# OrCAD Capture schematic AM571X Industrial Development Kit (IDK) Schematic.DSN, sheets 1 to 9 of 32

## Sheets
1 Pg23: USB JTAG: size C; title: AM571x Industrial Development Kit (IDK) EVM - TMDXIDK5718; rev: 1.3B; company: Texas Instruments; note: 3M0000; note: Catalog Processors BU; note: Final
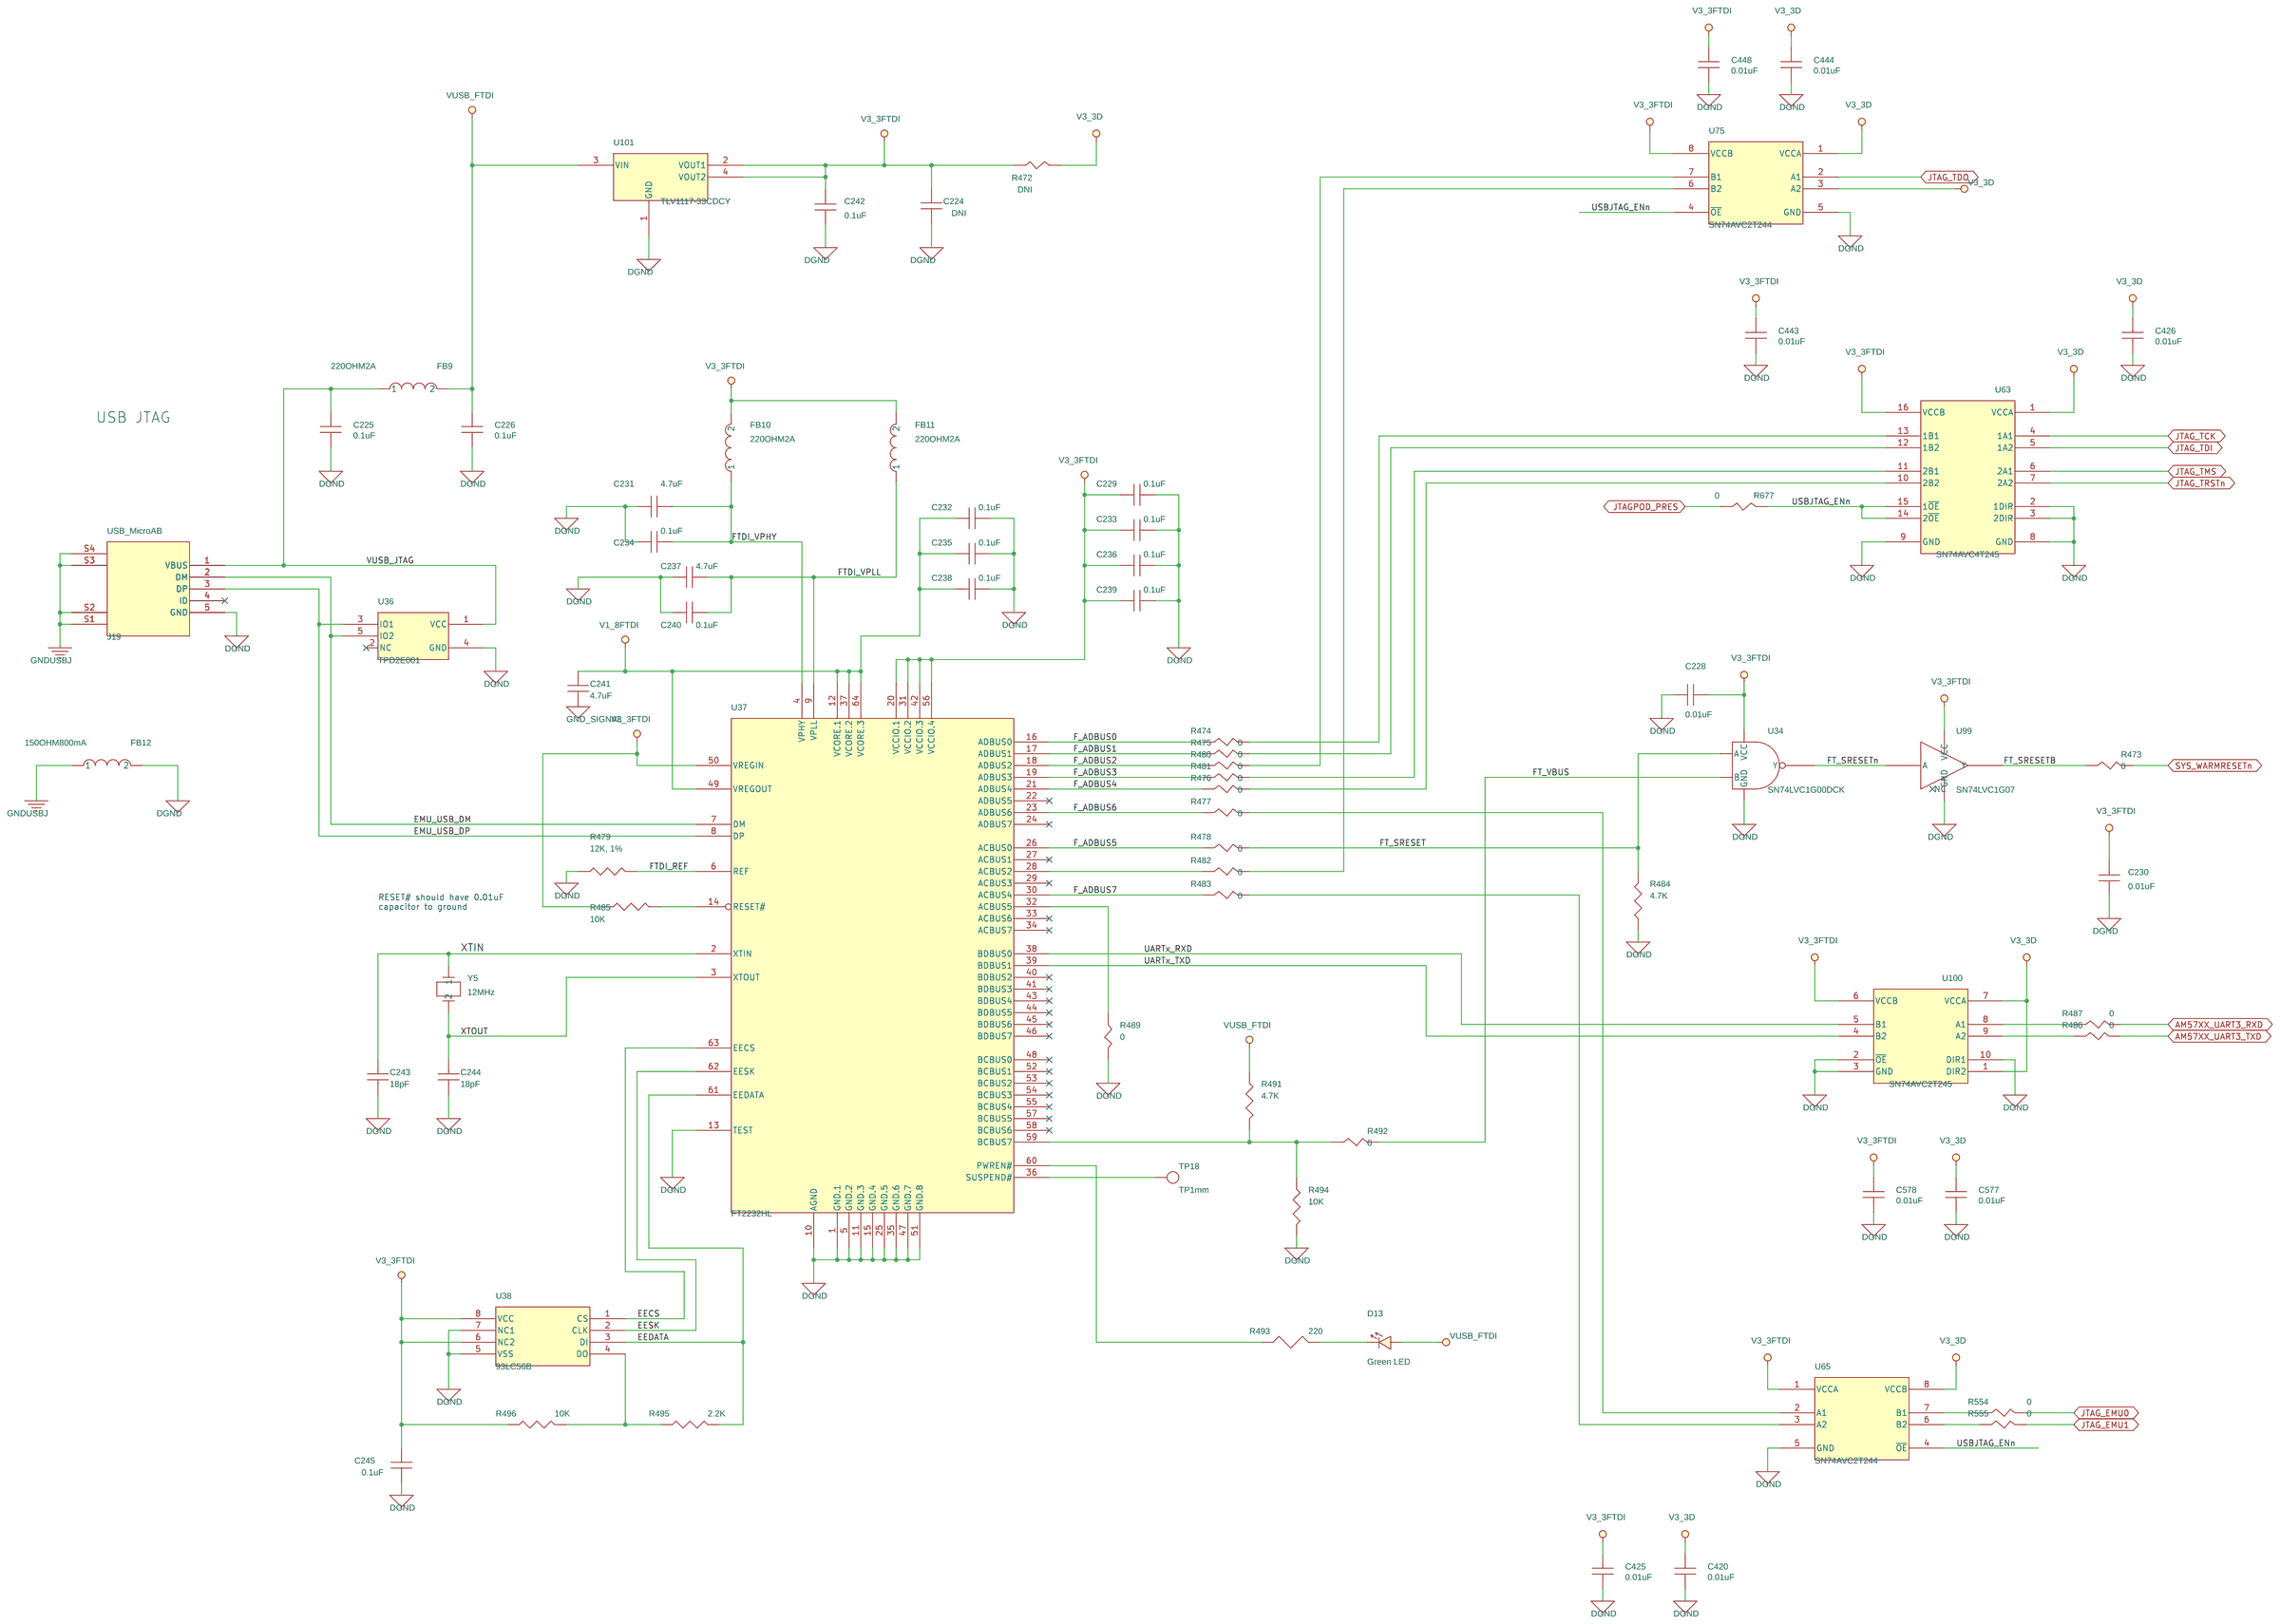
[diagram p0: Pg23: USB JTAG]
2 Pg24: eMMC: size C
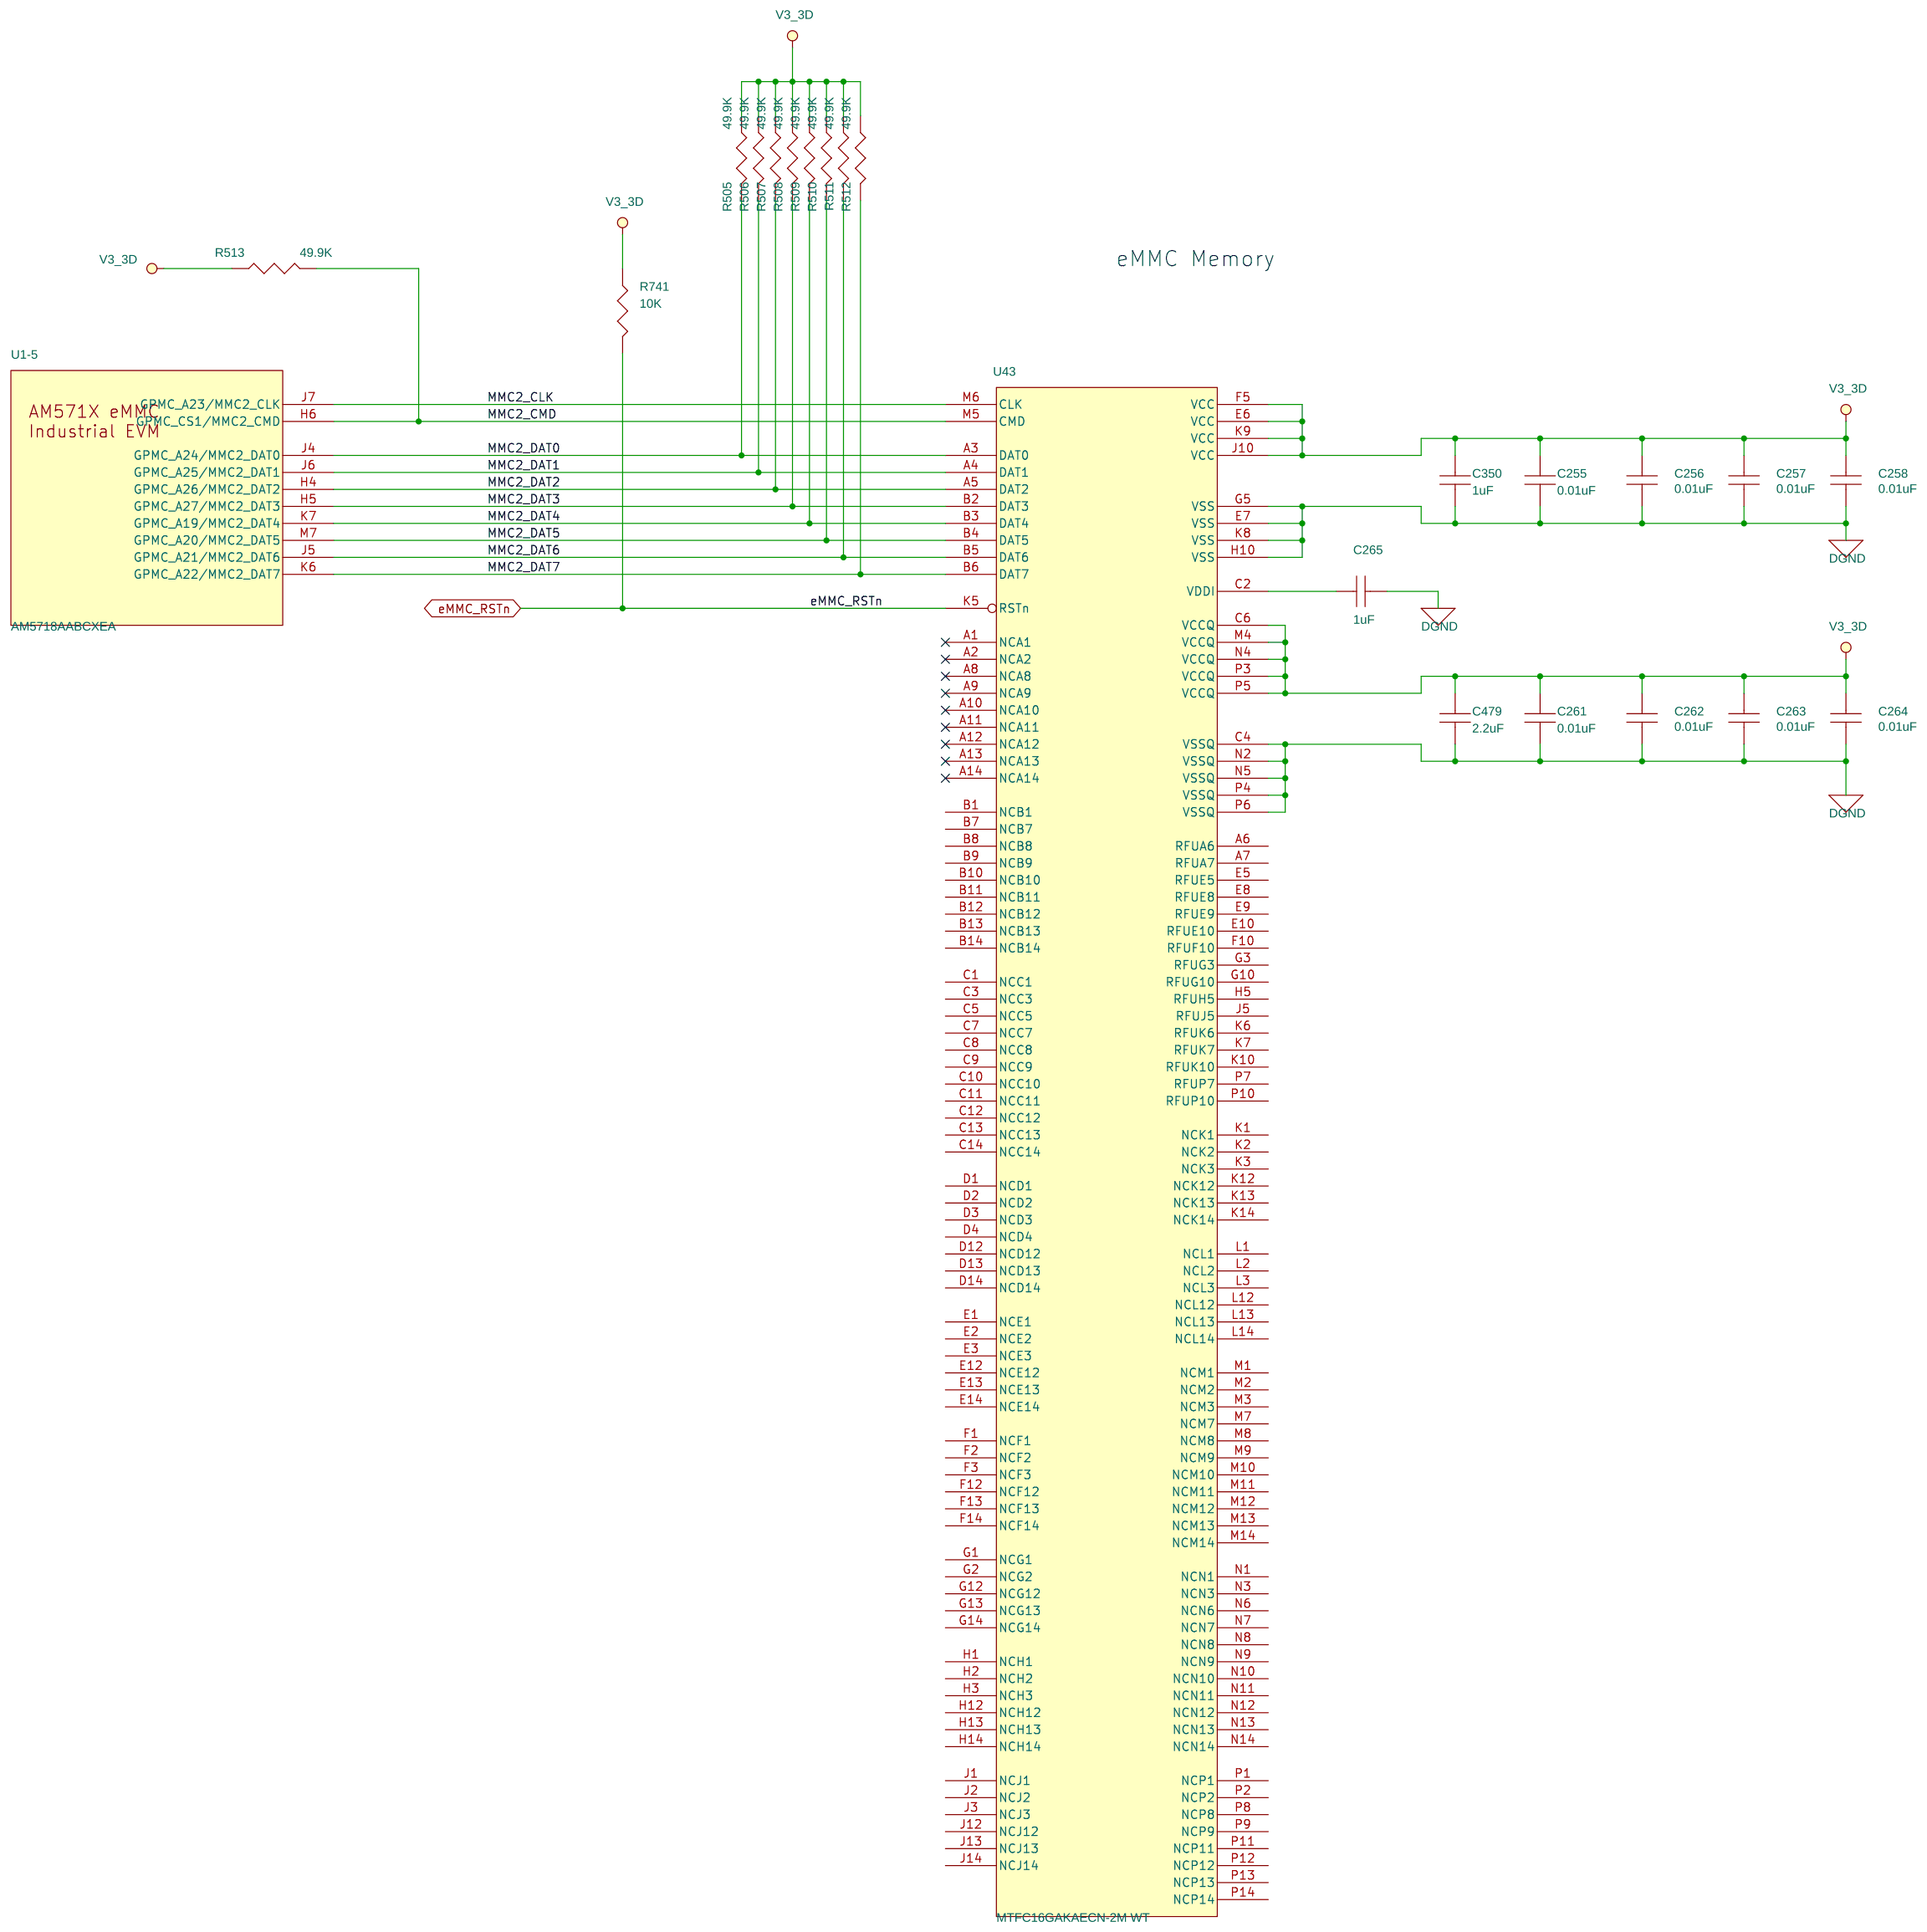
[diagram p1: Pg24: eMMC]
3 Pg31: RTC: size C
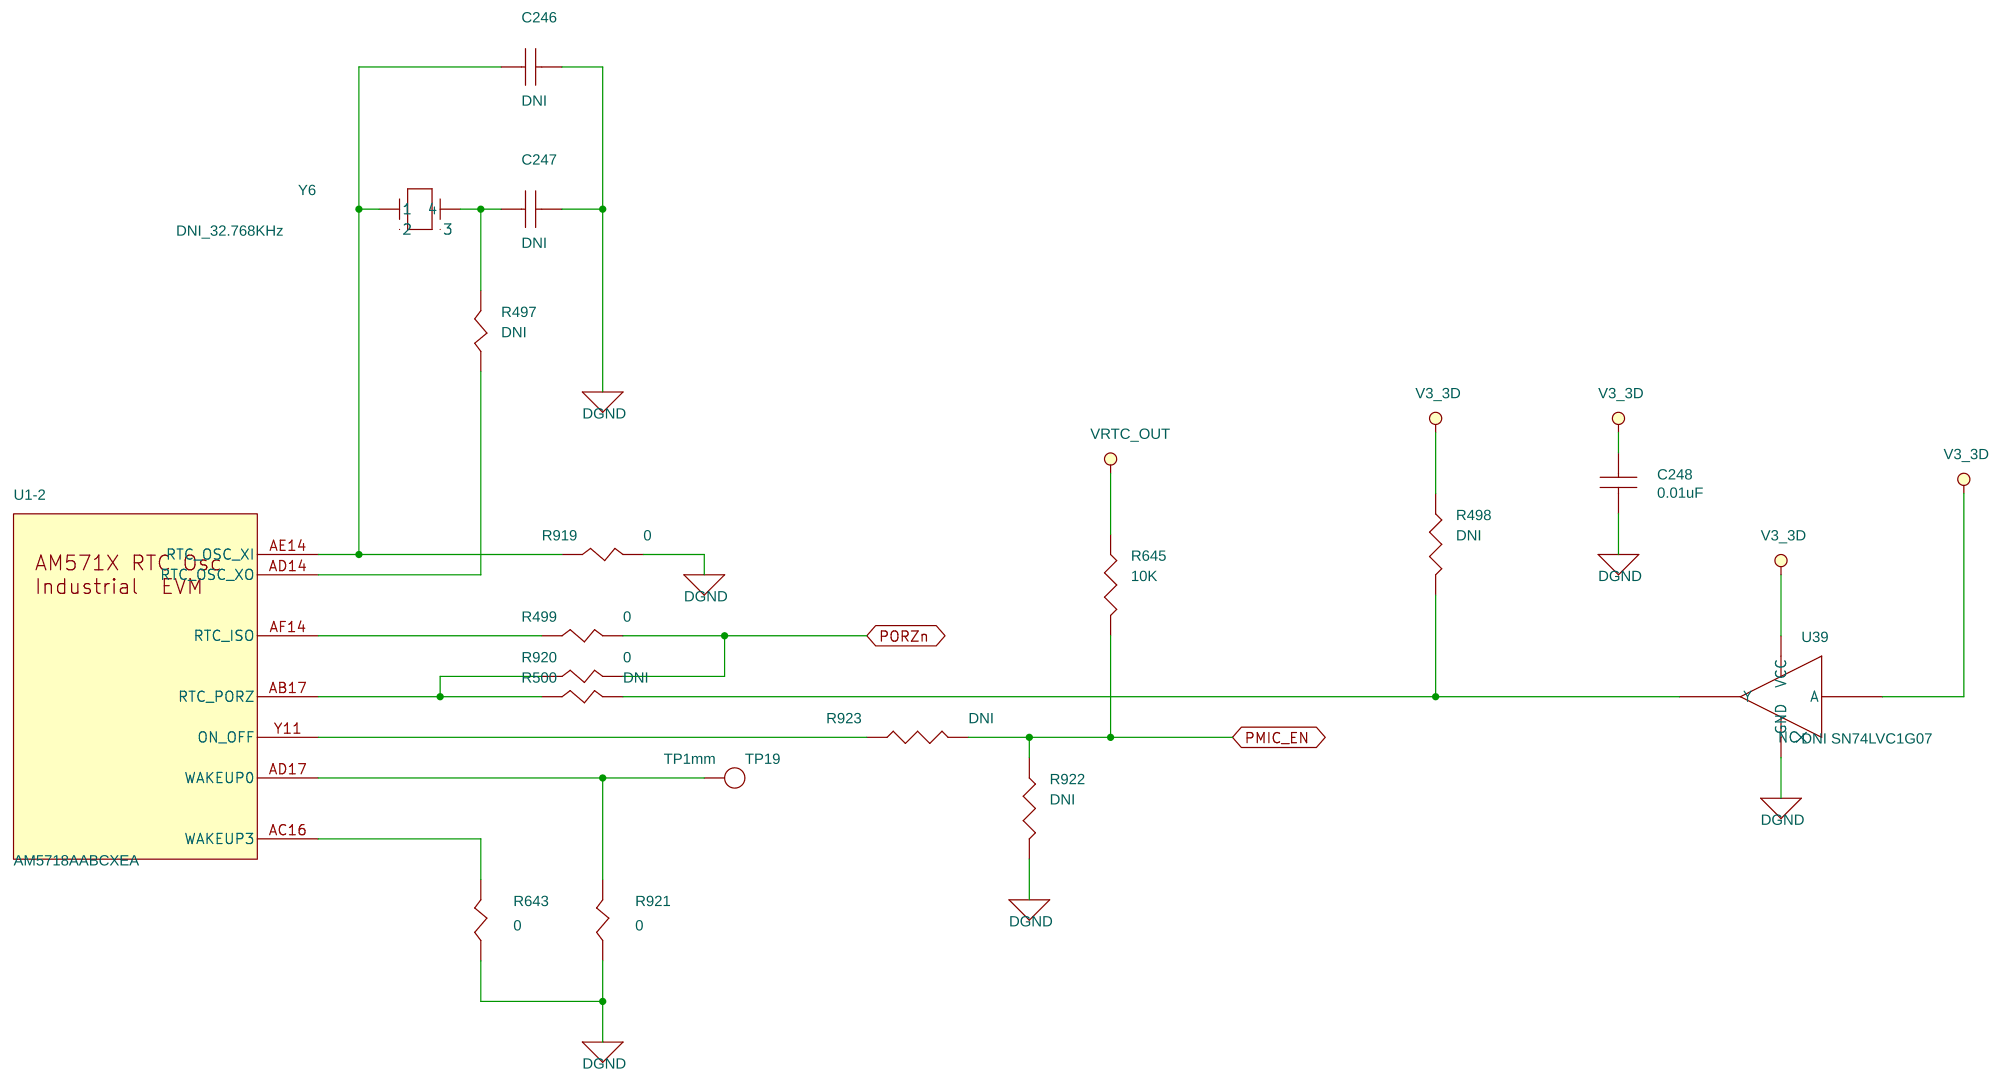
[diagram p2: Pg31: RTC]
4 Pg20: LCD: size C
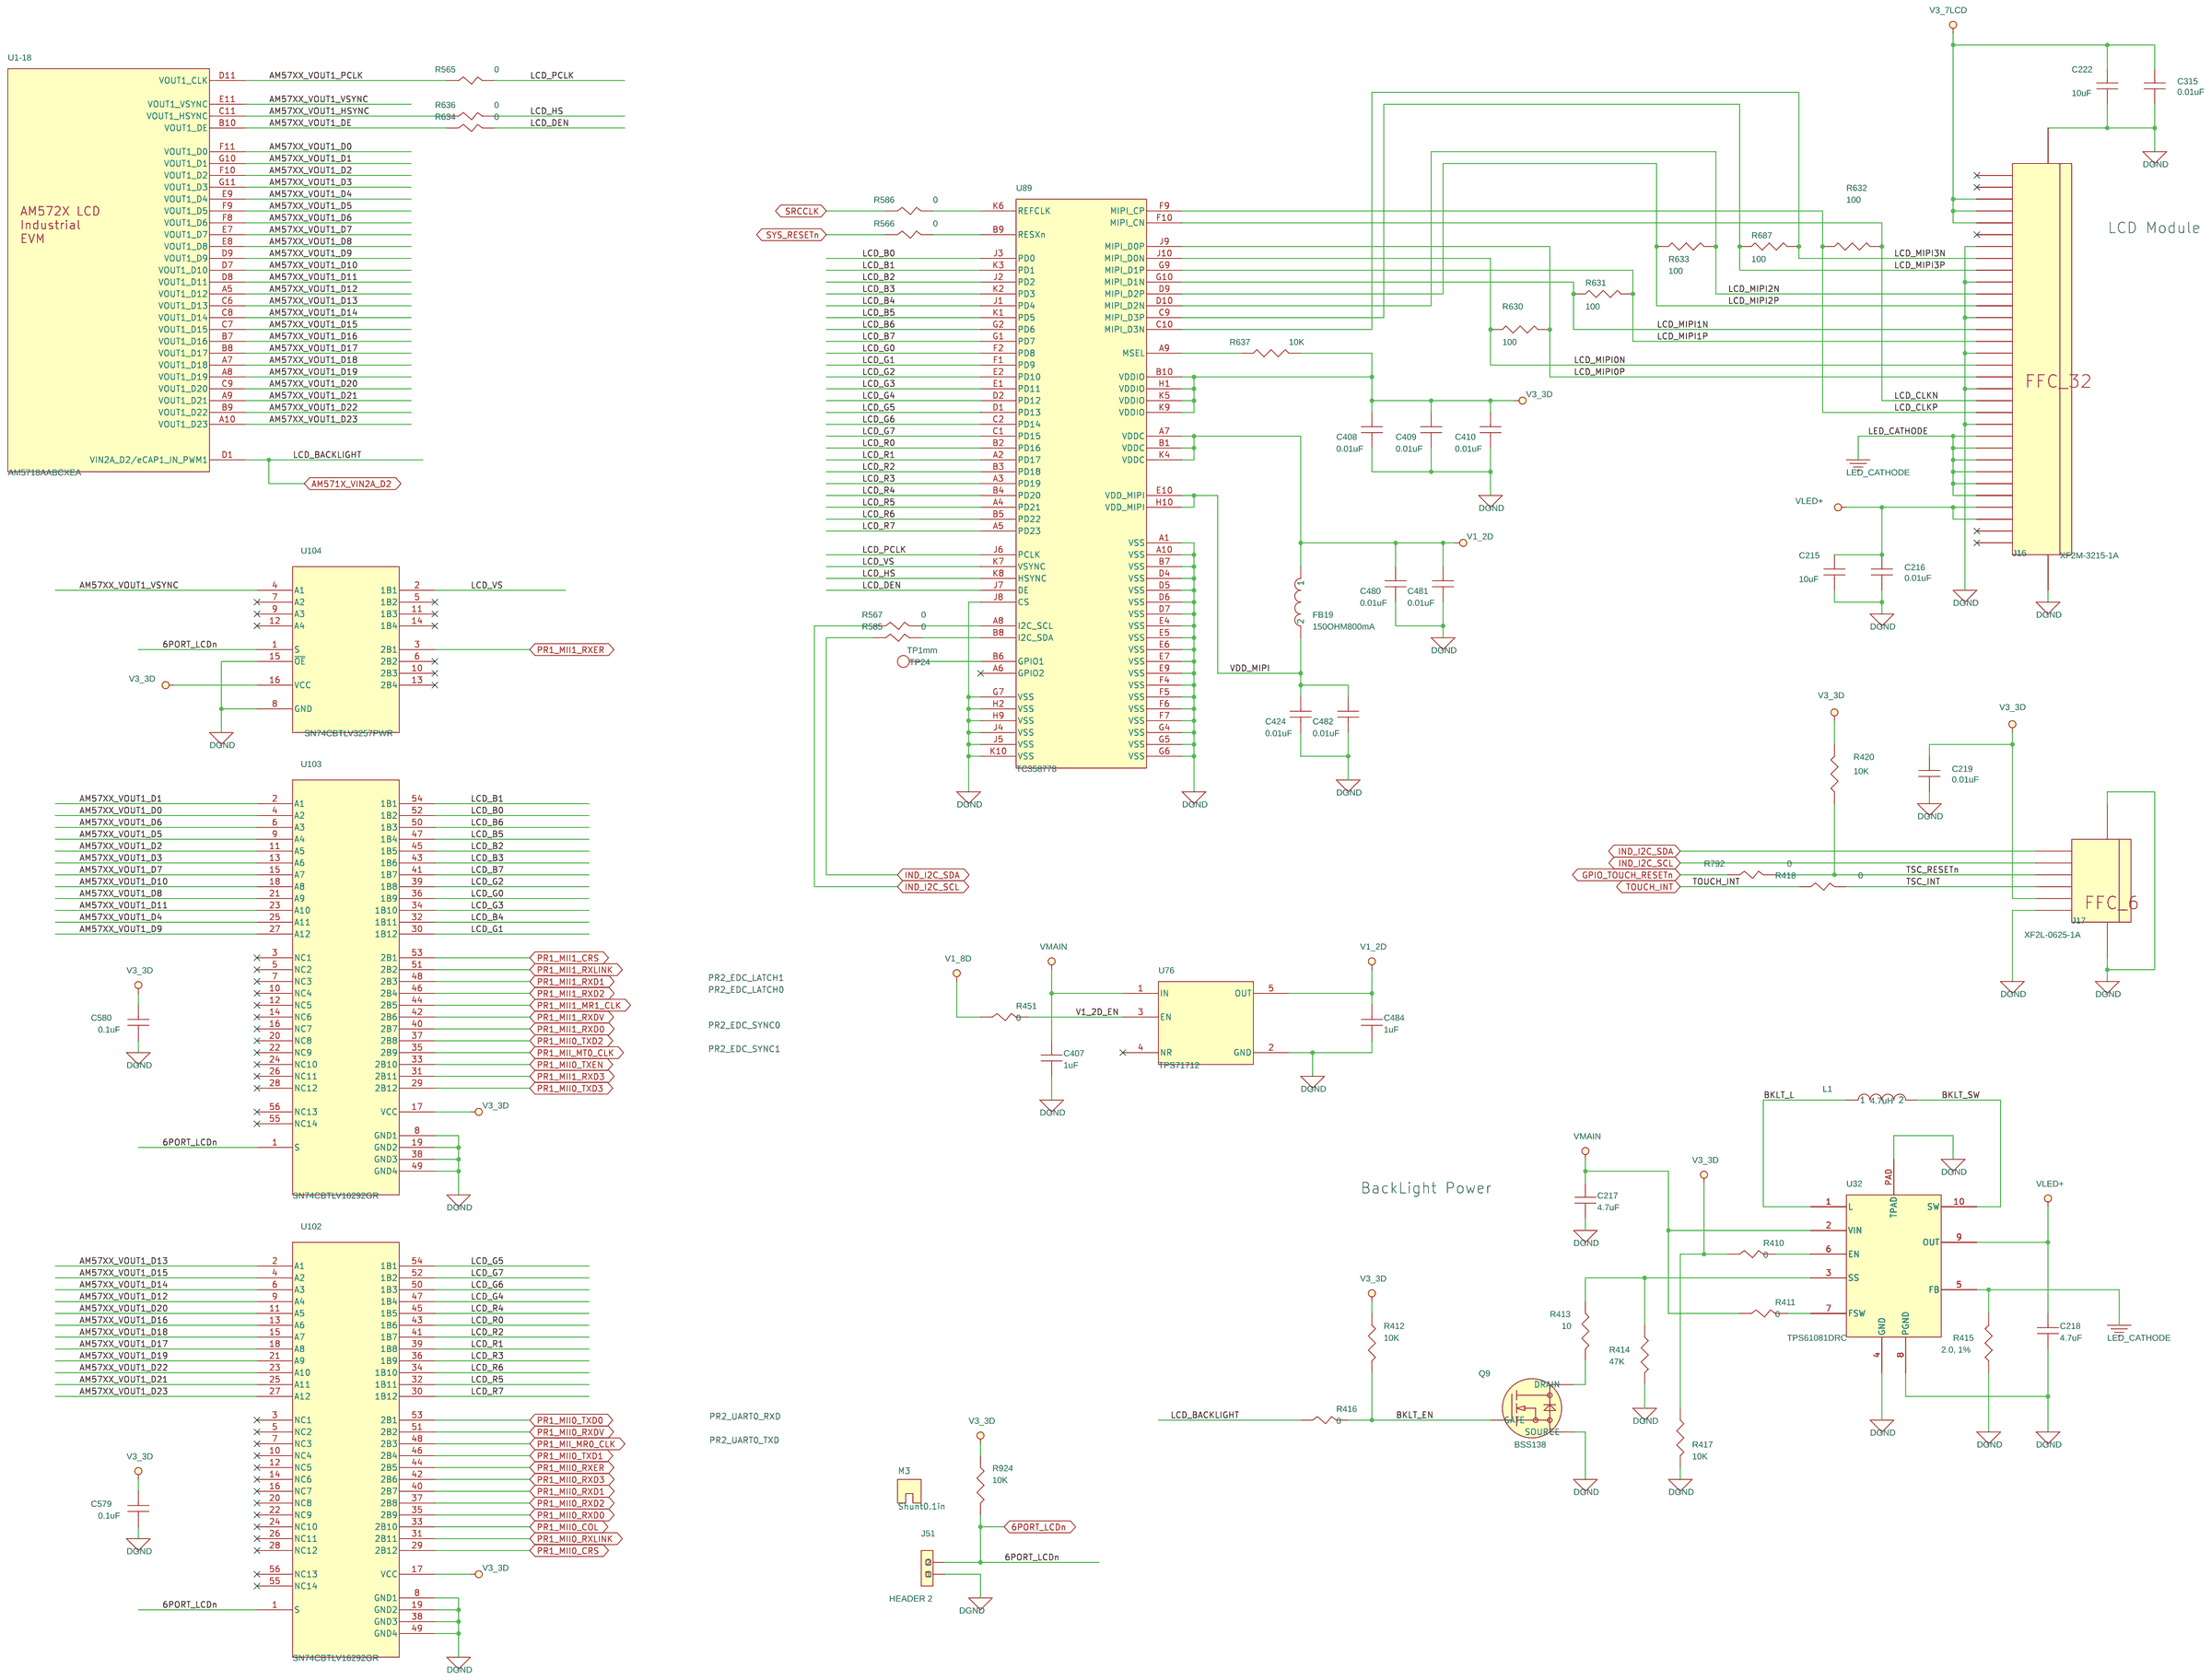
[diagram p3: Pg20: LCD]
5 Pg21: HDMI: size C
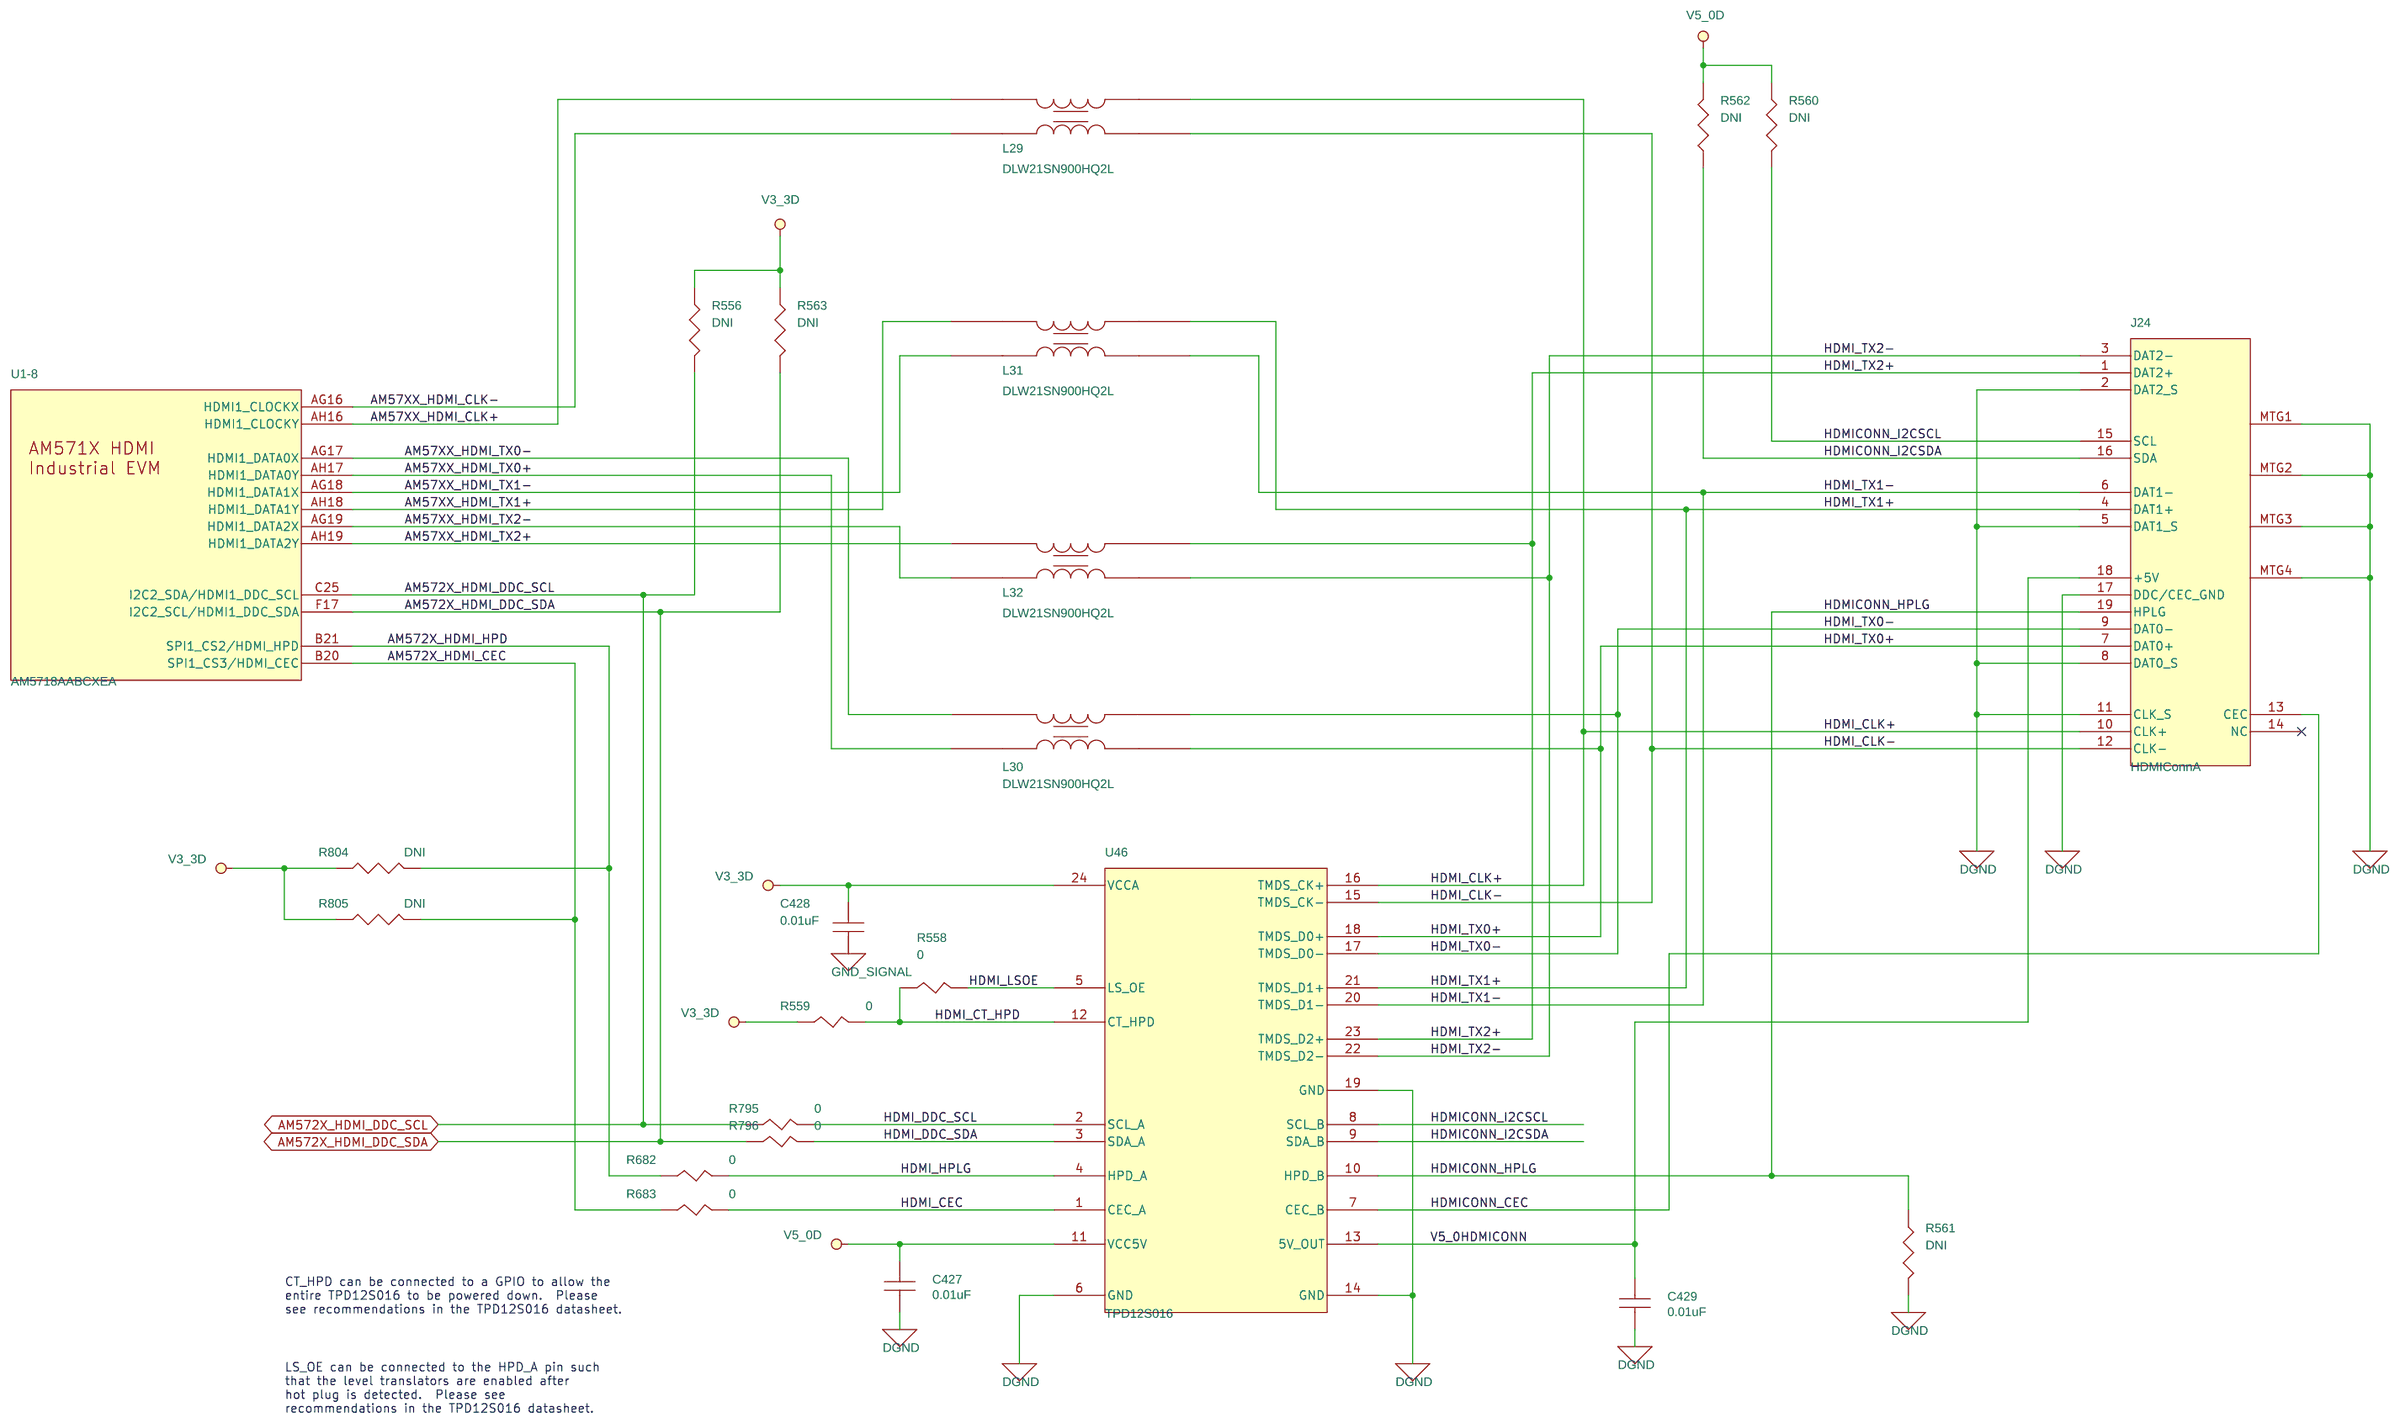
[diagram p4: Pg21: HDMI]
6 Pg27: DCAN #1: size C
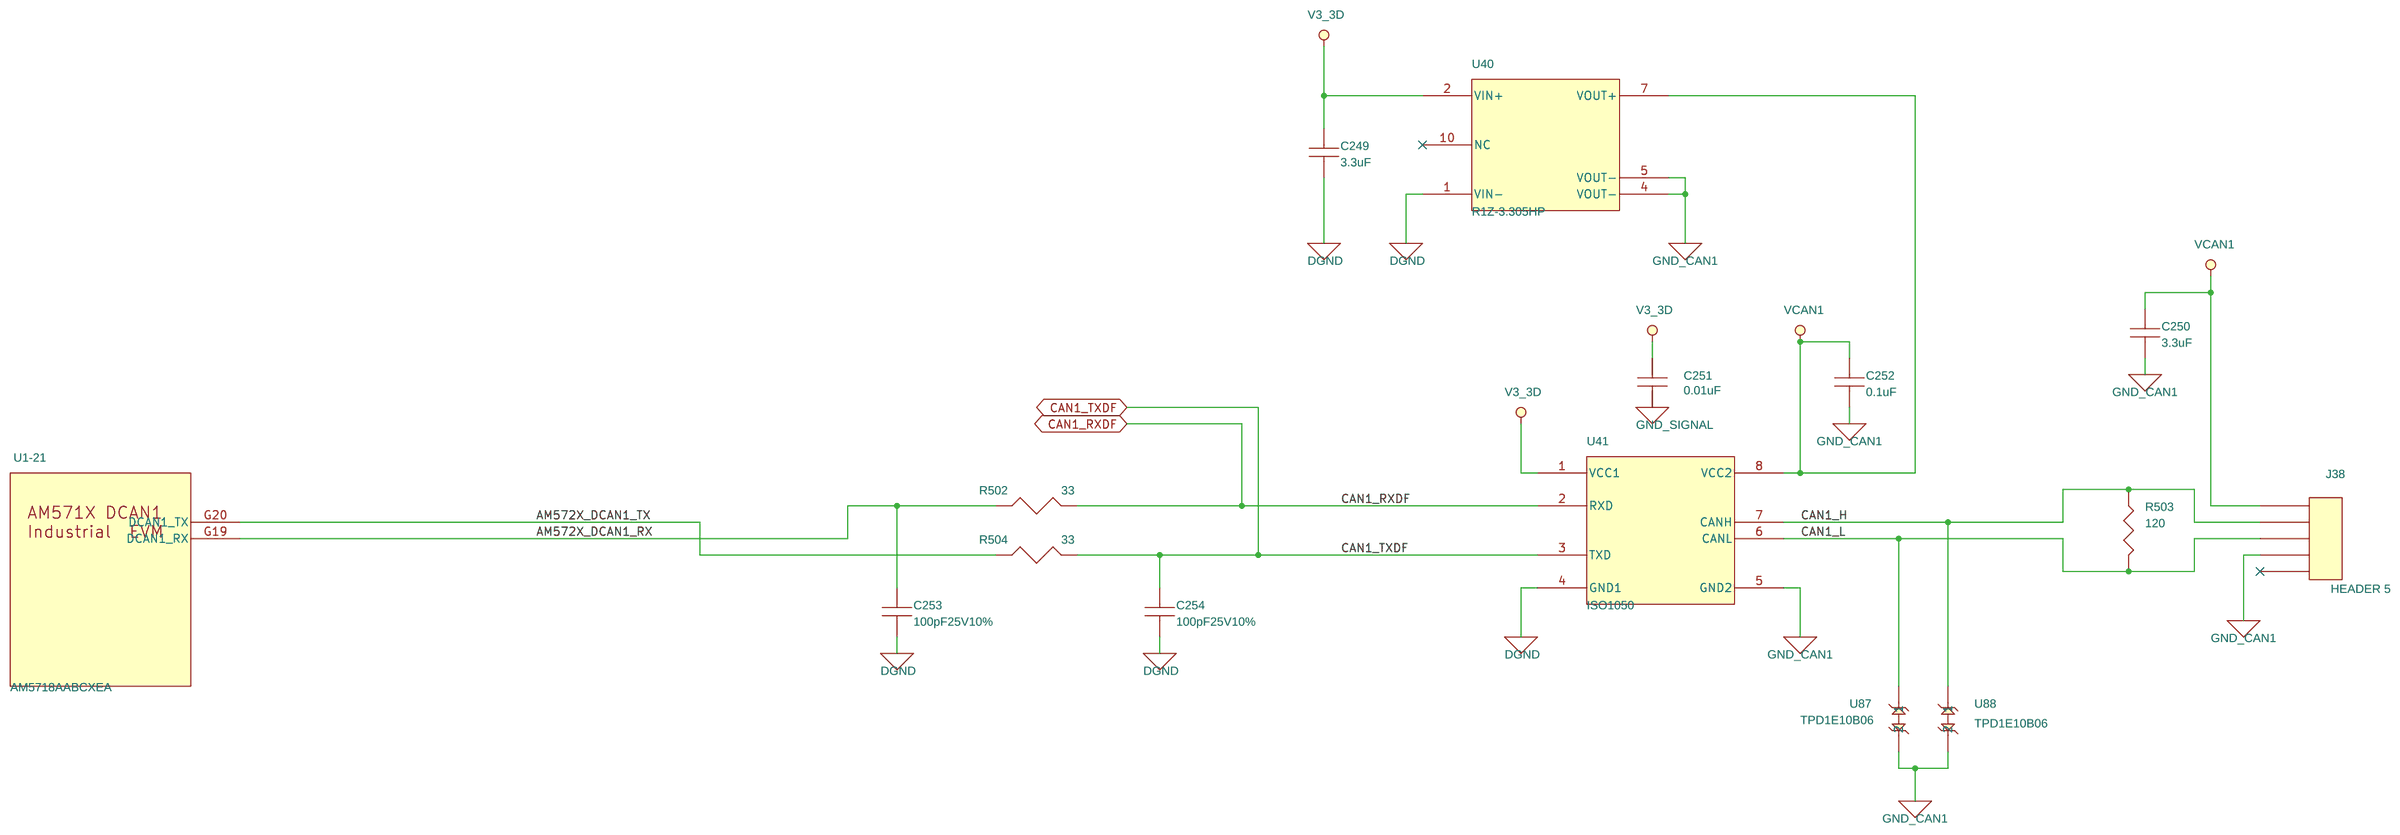
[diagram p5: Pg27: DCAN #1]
7 Pg29: RS-485: size C
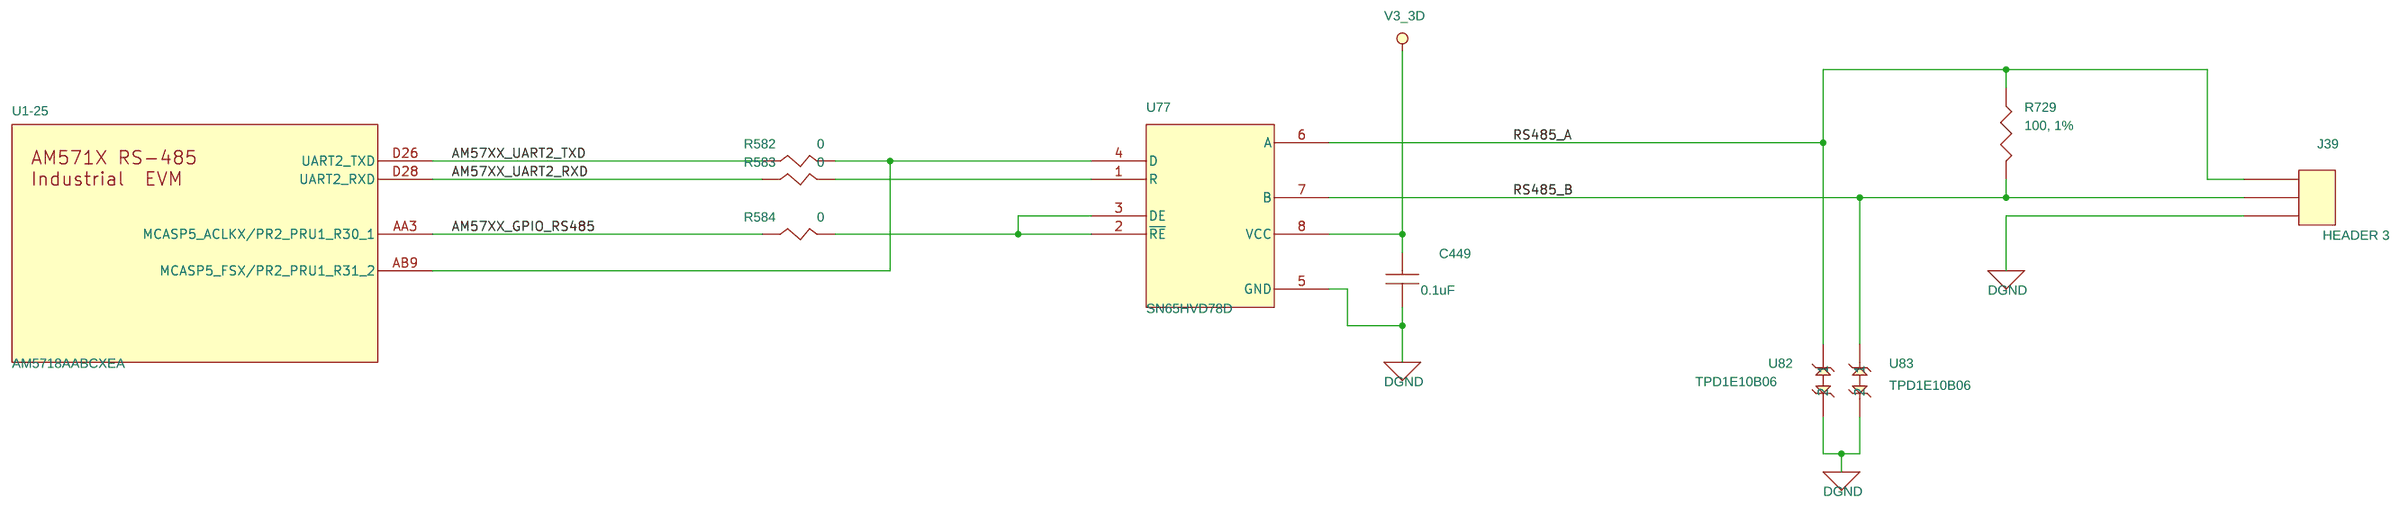
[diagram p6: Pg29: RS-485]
8 Pg09: DDR3 VTT: size C
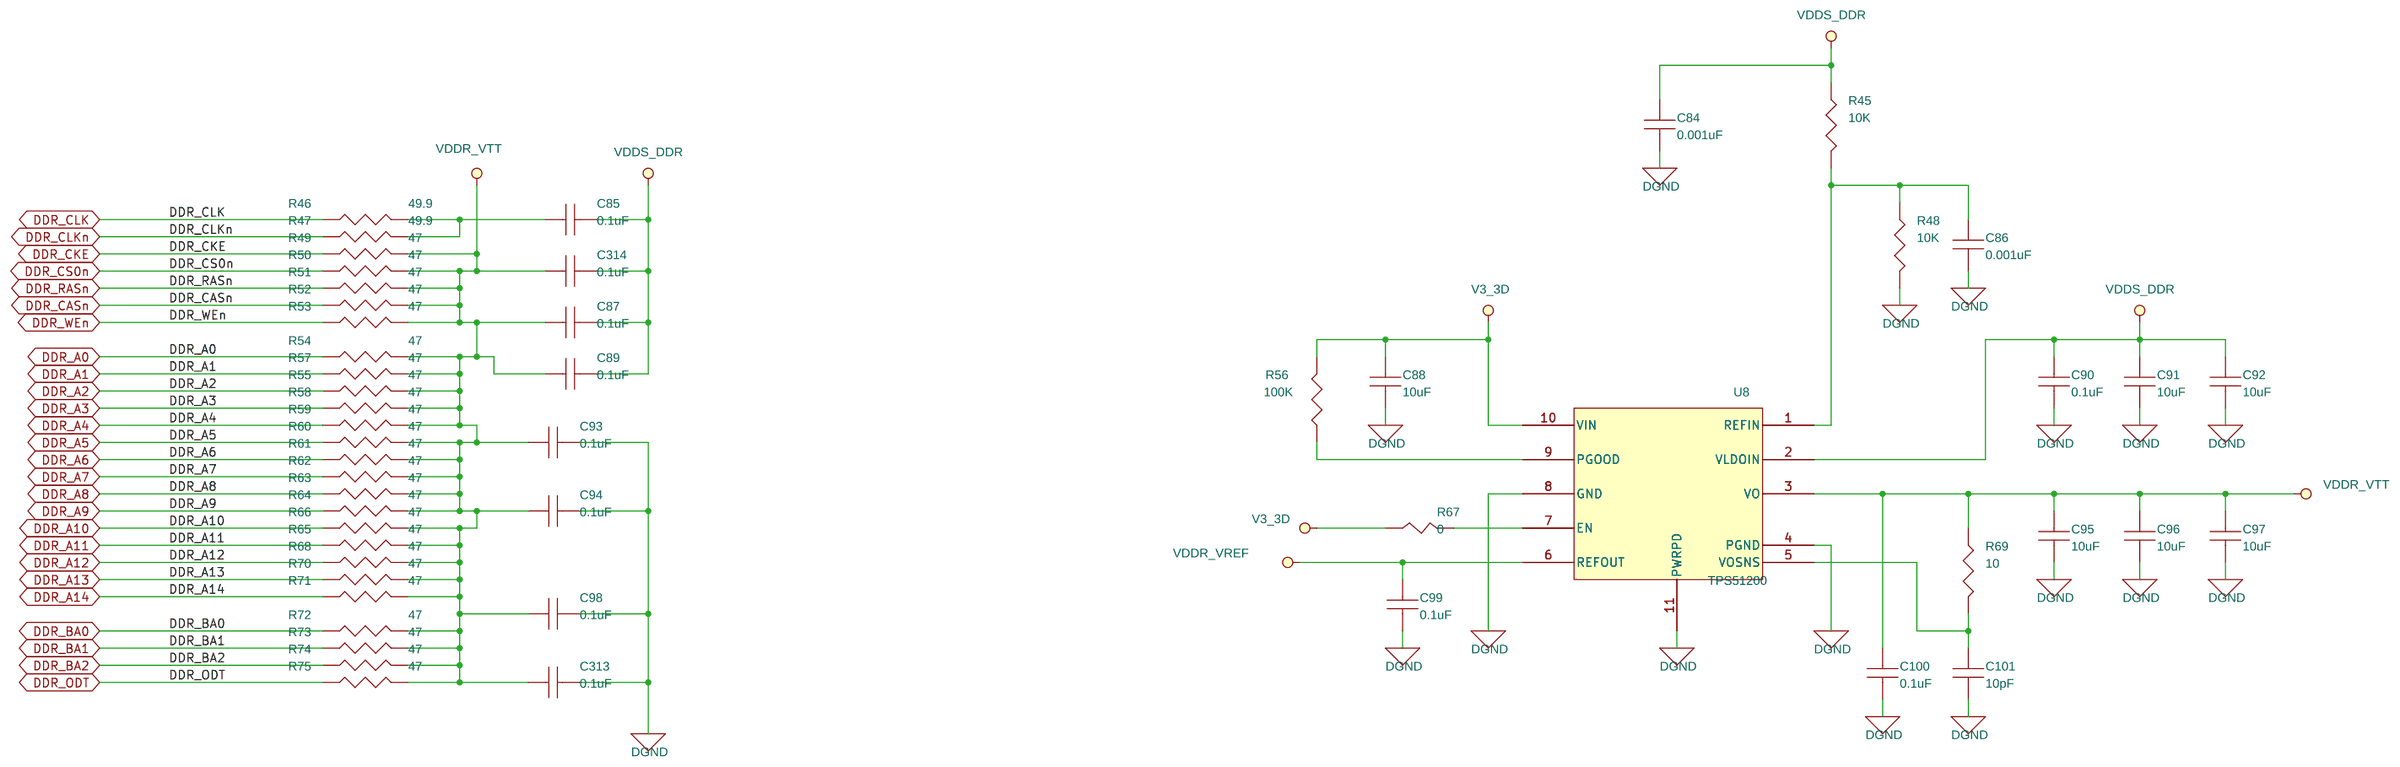
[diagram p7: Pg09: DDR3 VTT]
9 Pg05: Power Supply 1: size C
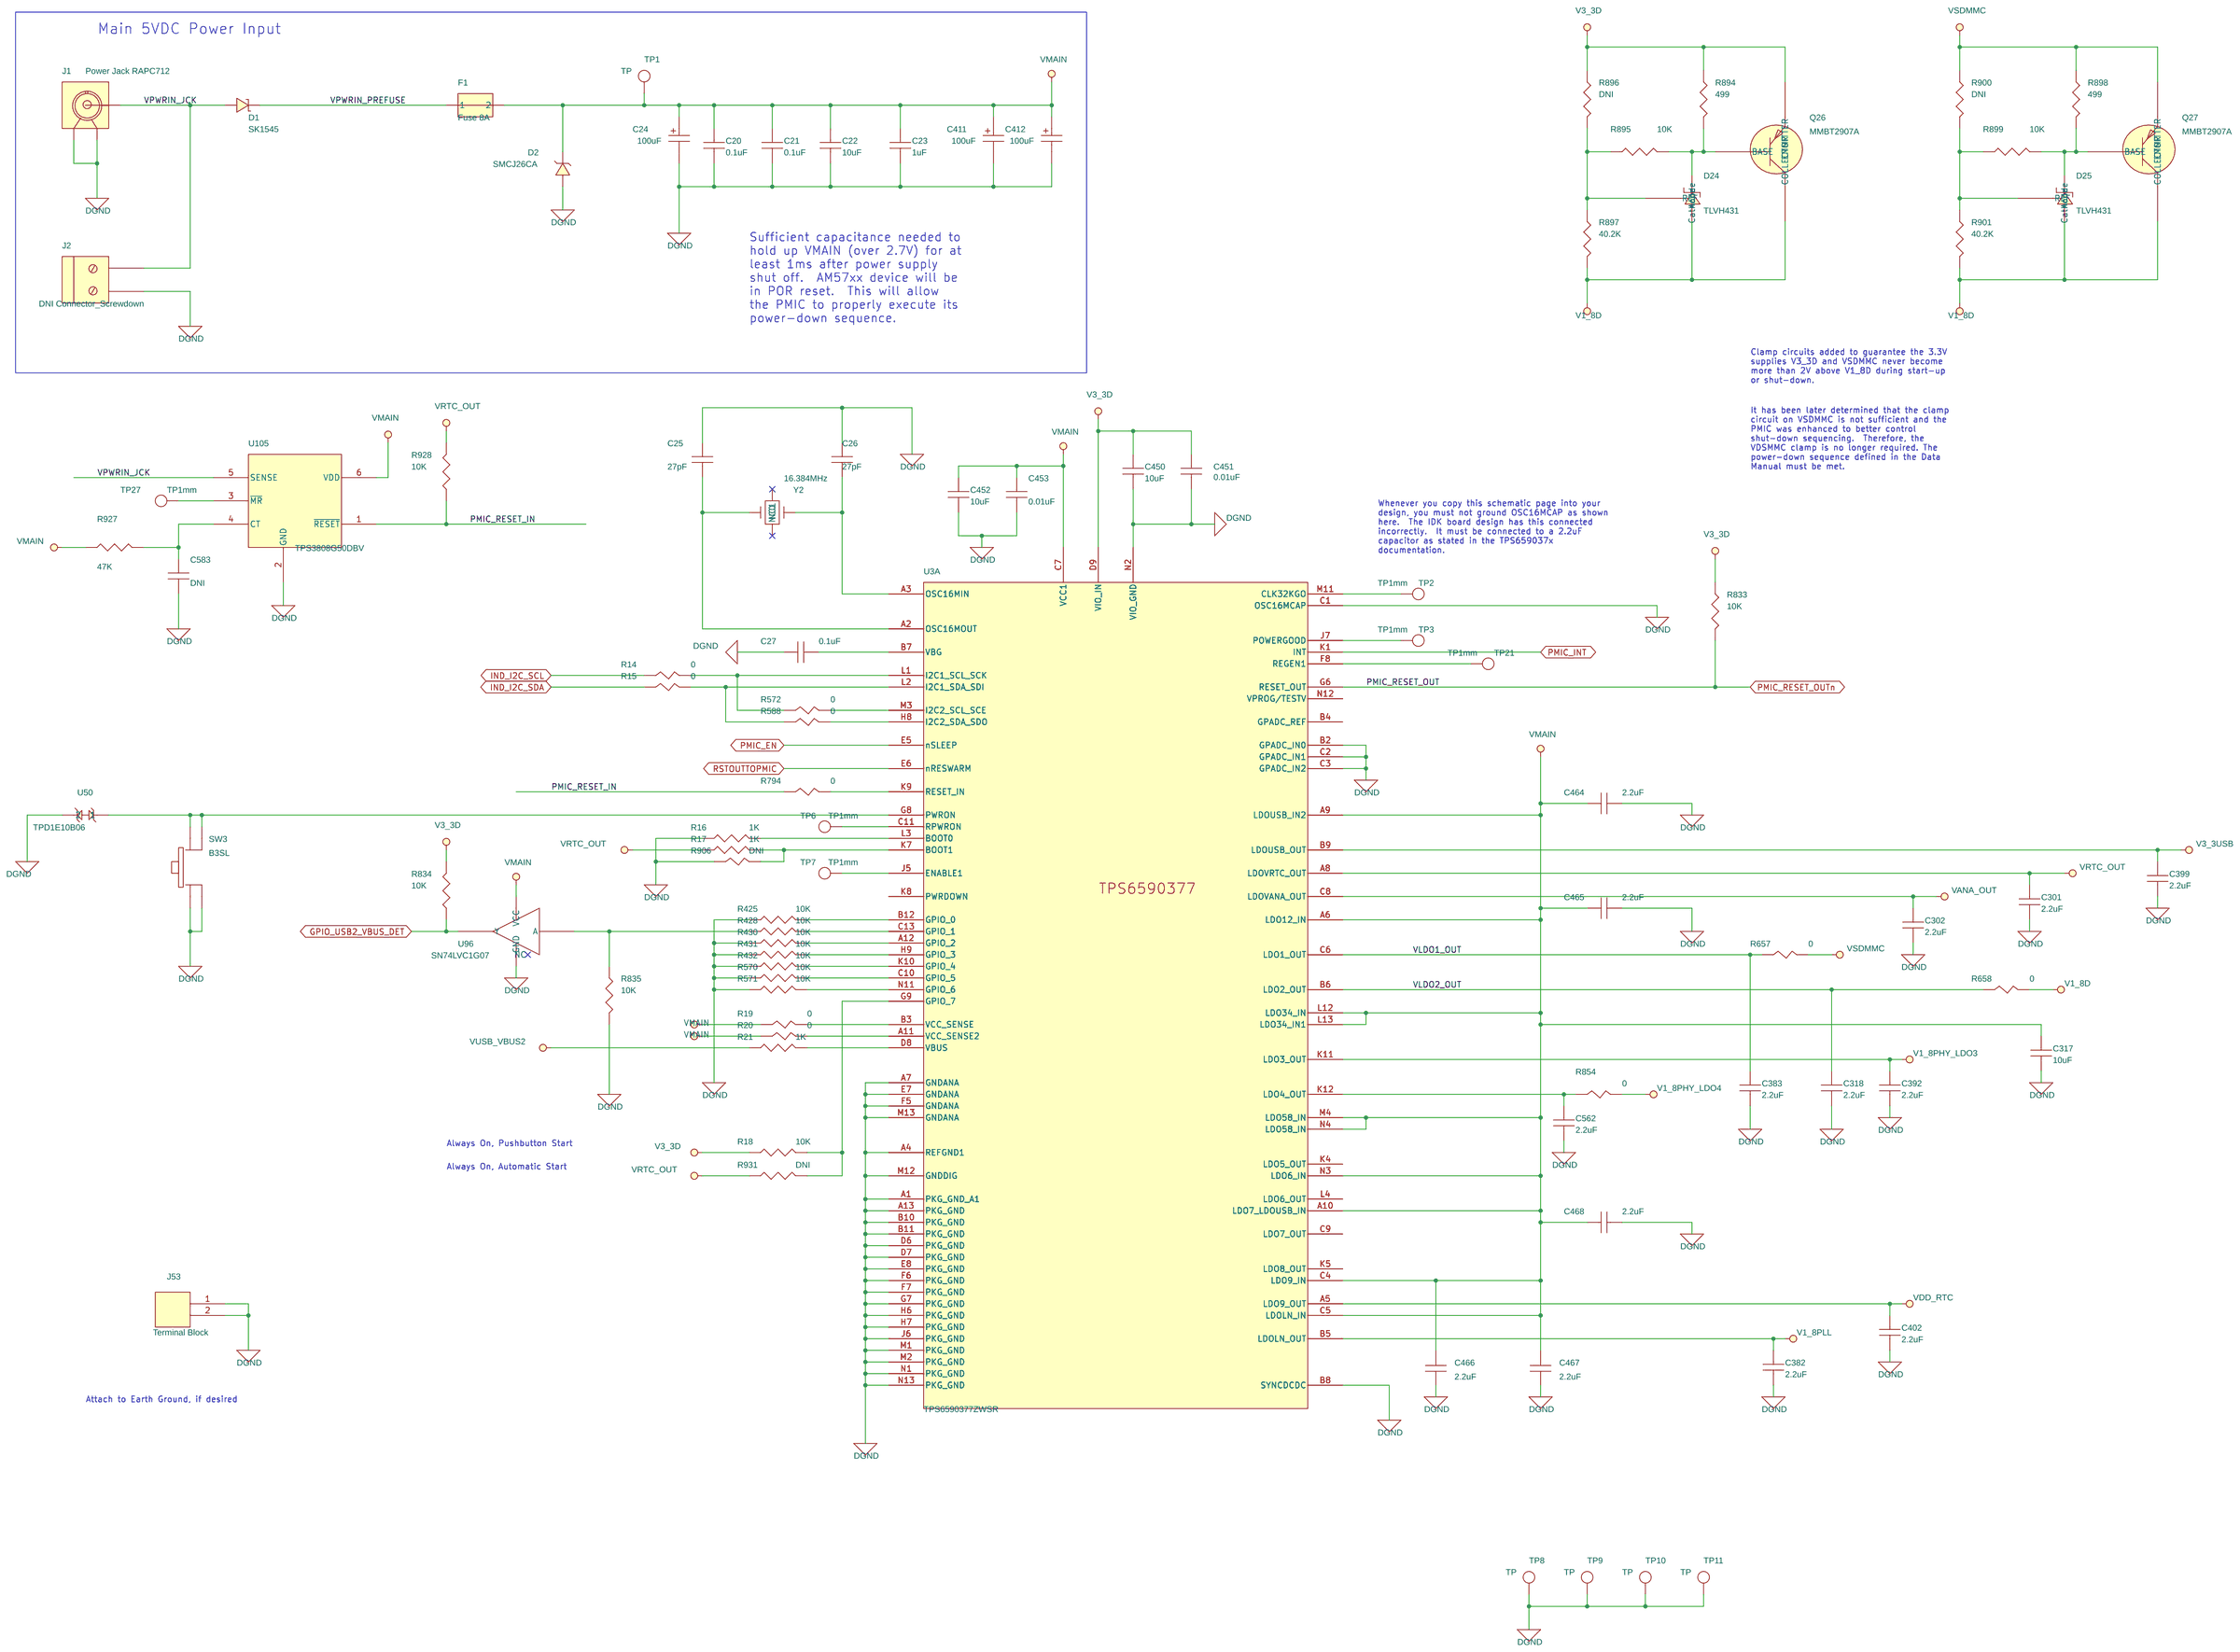
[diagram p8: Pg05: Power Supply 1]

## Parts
sheet Pg05: Power Supply 1
C20  0.1uF  [SM-7351-CAP-0402]
C21  0.1uF  [SM-7351-CAP-0402]
C22  10uF  [SM-7351-CAP-0805]
C23  1uF  [SM-7351-CAP-0603]
C24  100uF  [SM-7351-CAP-smdcan]
C25  27pF  [SM-7351-CAP-0402]
C26  27pF  [SM-7351-CAP-0402]
C27  0.1uF  [SM-7351-CAP-0402]
C301  2.2uF  [SM-7351-CAP-0402]
C302  2.2uF  [SM-7351-CAP-0402]
C317  10uF  [SM-7351-CAP-0805]
C318  2.2uF  [SM-7351-CAP-0402]
C382  2.2uF  [SM-7351-CAP-0402]
C383  2.2uF  [SM-7351-CAP-0402]
C392  2.2uF  [SM-7351-CAP-0402]
C399  2.2uF  [SM-7351-CAP-0402]
C402  2.2uF  [SM-7351-CAP-0402]
C411  100uF  [SM-7351-CAP-smdcan]
C412  100uF  [SM-7351-CAP-smdcan]
C450  10uF  [SM-7351-CAP-0603]
C451  0.01uF  [SM-7351-CAP-0402]
C452  10uF  [SM-7351-CAP-0603]
C453  0.01uF  [SM-7351-CAP-0402]
C464  2.2uF  [SM-7351-CAP-0805]
C465  2.2uF  [SM-7351-CAP-0805]
C466  2.2uF  [SM-7351-CAP-0805]
C467  2.2uF  [SM-7351-CAP-0805]
C468  2.2uF  [SM-7351-CAP-0805]
C562  2.2uF  [SM-7351-CAP-0402]
C583  DNI  [SM-7351-CAP-0402]
D1  SK1545  [sk1545]
D2  SMCJ26CA  [SMCJ26CA]
D24  TLVH431  [sot23-3-44m]
D25  TLVH431  [sot23-3-44m]
F1  Fuse 8A  [fuse-0154]
J1  Power Jack RAPC712  [RAPC712]
J2  DNI Connector_Screwdown  [conn_osttc02]
J53  Terminal Block  [CN1792216]
Q26  MMBT2907A  [sot23-3-44m]
Q27  MMBT2907A  [sot23-3-44m]
R14  0  [SM-7351-RES-0402]
R15  0  [SM-7351-RES-0402]
R16  1K  [SM-7351-RES-0402]
R17  1K  [SM-7351-RES-0402]
R18  10K  [SM-7351-RES-0402]
R19  0  [SM-7351-RES-0402]
R20  0  [SM-7351-RES-0402]
R21  1K  [SM-7351-RES-0402]
R425  10K  [SM-7351-RES-0402]
R428  10K  [SM-7351-RES-0402]
R430  10K  [SM-7351-RES-0402]
R431  10K  [SM-7351-RES-0402]
R432  10K  [SM-7351-RES-0402]
R570  10K  [SM-7351-RES-0402]
R571  10K  [SM-7351-RES-0402]
R572  0  [SM-7351-RES-0402]
R588  0  [SM-7351-RES-0402]
R657  0  [SM-7351-RES-0402]
R658  0  [SM-7351-RES-0402]
R794  0  [SM-7351-RES-0402]
R833  10K  [SM-7351-RES-0402]
R834  10K  [SM-7351-RES-0402]
R835  10K  [SM-7351-RES-0402]
R854  0  [SM-7351-RES-0402]
R894  499  [SM-7351-RES-0402]
R895  10K  [SM-7351-RES-0402]
R896  DNI  [SM-7351-RES-0402]
R897  40.2K  [SM-7351-RES-0402]
R898  499  [SM-7351-RES-0402]
R899  10K  [SM-7351-RES-0402]
R900  DNI  [SM-7351-RES-0402]
R901  40.2K  [SM-7351-RES-0402]
R906  DNI  [SM-7351-RES-0402]
R927  47K  [SM-7351-RES-0402]
R928  10K  [SM-7351-RES-0402]
R931  DNI  [SM-7351-RES-0402]
SW3  B3SL  [SW_B3SL-1022P]
TP1  TP  [TH_TP_5002]
TP2  TP1mm  [tp_smd1mmcircle]
TP3  TP1mm  [tp_smd1mmcircle]
TP6  TP1mm  [tp_smd1mmcircle]
TP7  TP1mm  [tp_smd1mmcircle]
TP8  TP  [TH_TP_5002]
TP9  TP  [TH_TP_5002]
TP10  TP  [TH_TP_5002]
TP11  TP  [TH_TP_5002]
TP21  TP1mm  [tp_smd1mmcircle]
TP27  TP1mm  [tp_smd1mmcircle]
U50  TPD1E10B06  [tpd1e10b06-2l]
U96  SN74LVC1G07  [SC70-5-43M]
U105  TPS3808G50DBV  [U_6_DBV]
Y2  16.384MHz  [xtal3225-39m]
sheet Pg06: Power Supply 2
U3  TPS6590377ZWSR  [bga12x12-169-55m]  (sections A,B)
sheet Pg09: DDR3 VTT
C84  0.001uF  [SM-7351-CAP-0402]
C85  0.1uF  [SM-7351-CAP-0402]
C86  0.001uF  [SM-7351-CAP-0402]
C87  0.1uF  [SM-7351-CAP-0402]
C88  10uF  [SM-7351-CAP-0805]
C89  0.1uF  [SM-7351-CAP-0402]
C90  0.1uF  [SM-7351-CAP-0402]
C91  10uF  [SM-7351-CAP-0805]
C92  10uF  [SM-7351-CAP-0805]
C93  0.1uF  [SM-7351-CAP-0402]
C94  0.1uF  [SM-7351-CAP-0402]
C95  10uF  [SM-7351-CAP-0805]
C96  10uF  [SM-7351-CAP-0805]
C97  10uF  [SM-7351-CAP-0805]
C98  0.1uF  [SM-7351-CAP-0402]
C99  0.1uF  [SM-7351-CAP-0402]
C100  0.1uF  [SM-7351-CAP-0402]
C101  10pF  [SM-7351-CAP-0402]
C313  0.1uF  [SM-7351-CAP-0402]
C314  0.1uF  [SM-7351-CAP-0402]
R45  10K  [SM-7351-RES-0402]
R46  49.9  [SM-7351-RES-0402]
R47  49.9  [SM-7351-RES-0402]
R48  10K  [SM-7351-RES-0402]
R49  47  [SM-7351-RES-0402]
R50  47  [SM-7351-RES-0402]
R51  47  [SM-7351-RES-0402]
R52  47  [SM-7351-RES-0402]
R53  47  [SM-7351-RES-0402]
R54  47  [SM-7351-RES-0402]
R55  47  [SM-7351-RES-0402]
R56  100K  [SM-7351-RES-0402]
R57  47  [SM-7351-RES-0402]
R58  47  [SM-7351-RES-0402]
R59  47  [SM-7351-RES-0402]
R60  47  [SM-7351-RES-0402]
R61  47  [SM-7351-RES-0402]
R62  47  [SM-7351-RES-0402]
R63  47  [SM-7351-RES-0402]
R64  47  [SM-7351-RES-0402]
R65  47  [SM-7351-RES-0402]
R66  47  [SM-7351-RES-0402]
R67  0  [SM-7351-RES-0402]
R68  47  [SM-7351-RES-0402]
R69  10  [SM-7351-RES-0402]
R70  47  [SM-7351-RES-0402]
R71  47  [SM-7351-RES-0402]
R72  47  [SM-7351-RES-0402]
R73  47  [SM-7351-RES-0402]
R74  47  [SM-7351-RES-0402]
R75  47  [SM-7351-RES-0402]
U8  TPS51200  [drcpso_10pin]
sheet Pg20: LCD
C215  10uF  [SM-7351-CAP-0805]
C216  0.01uF  [SM-7351-CAP-0402]
C217  4.7uF  [SM-7351-CAP-0603]
C218  4.7uF  [SM-7351-CAP-0805]
C219  0.01uF  [SM-7351-CAP-0402]
C222  10uF  [SM-7351-CAP-0805]
C315  0.01uF  [SM-7351-CAP-0402]
C407  1uF  [SM-7351-CAP-0402]
C408  0.01uF  [SM-7351-CAP-0402]
C409  0.01uF  [SM-7351-CAP-0402]
C410  0.01uF  [SM-7351-CAP-0402]
C424  0.01uF  [SM-7351-CAP-0402]
C480  0.01uF  [SM-7351-CAP-0402]
C481  0.01uF  [SM-7351-CAP-0402]
C482  0.01uF  [SM-7351-CAP-0402]
C484  1uF  [SM-7351-CAP-0402]
C579  0.1uF  [SM-7351-CAP-0402]
C580  0.1uF  [SM-7351-CAP-0402]
FB19  150OHM800mA  [sm-7351-ind-0805]
J16  XF2M-3215-1A  [CNXF2M-3215-1A]
J17  XF2L-0625-1A  [CNXF2L-0625-1A]
J51  HEADER 2  [header_2x1]
L1  4.7uH  [vlcf5020t]
M3  Shunt0.1in  [none]
Q9  BSS138  [SOT23-3]
R410  0  [SM-7351-RES-0402]
R411  0  [SM-7351-RES-0402]
R412  10K  [SM-7351-RES-0402]
R413  10  [SM-7351-RES-0402]
R414  47K  [SM-7351-RES-0402]
R415  2.0, 1%  [SM-7351-RES-0603]
R416  0  [SM-7351-RES-0402]
R417  10K  [SM-7351-RES-0402]
R418  0  [SM-7351-RES-0402]
R420  10K  [SM-7351-RES-0402]
R451  0  [SM-7351-RES-0402]
R565  0  [SM-7351-RES-0402]
R566  0  [SM-7351-RES-0402]
R567  0  [SM-7351-RES-0402]
R585  0  [SM-7351-RES-0402]
R586  0  [SM-7351-RES-0402]
R630  100  [SM-7351-RES-0402]
R631  100  [SM-7351-RES-0402]
R632  100  [SM-7351-RES-0402]
R633  100  [SM-7351-RES-0402]
R634  0  [SM-7351-RES-0402]
R636  0  [SM-7351-RES-0402]
R637  10K  [SM-7351-RES-0402]
R687  100  [SM-7351-RES-0402]
R792  0  [SM-7351-RES-0402]
R924  10K  [SM-7351-RES-0402]
TP24  TP1mm  [tp_smd1mmcircle]
U32  TPS61081DRC  [u_10_drc]
U76  TPS71712  [smdsc70-5]
U89  TC358778  [BGA7X7-80-39M]
U102  SN74CBTLV16292GR  [TSSOP6X14-56-47M]
U103  SN74CBTLV16292GR  [TSSOP6X14-56-47M]
U104  SN74CBTLV3257PWR  [U_16_PW]
sheet Pg21: HDMI
C427  0.01uF  [SM-7351-CAP-0402]
C428  0.01uF  [SM-7351-CAP-0402]
C429  0.01uF  [SM-7351-CAP-0402]
J24  HDMIConnA  [smd_hdmia_ra]
L29  DLW21SN900HQ2L  [filt-dlw21s]
L30  DLW21SN900HQ2L  [filt-dlw21s]
L31  DLW21SN900HQ2L  [filt-dlw21s]
L32  DLW21SN900HQ2L  [filt-dlw21s]
R556  DNI  [sm-7351-res-0402]
R558  0  [SM-7351-RES-0402]
R559  0  [SM-7351-RES-0402]
R560  DNI  [SM-7351-RES-0402]
R561  DNI  [SM-7351-RES-0402]
R562  DNI  [SM-7351-RES-0402]
R563  DNI  [sm-7351-res-0402]
R682  0  [SM-7351-RES-0402]
R683  0  [SM-7351-RES-0402]
R795  0  [SM-7351-RES-0402]
R796  0  [SM-7351-RES-0402]
R804  DNI  [SM-7351-RES-0402]
R805  DNI  [SM-7351-RES-0402]
U46  TPD12S016  [pw_24pin_tssop]
sheet Pg23: USB JTAG
C224  DNI  [SM-7351-CAP-0805]
C225  0.1uF  [SM-7351-CAP-0402]
C226  0.1uF  [SM-7351-CAP-0402]
C228  0.01uF  [SM-7351-CAP-0402]
C229  0.1uF  [SM-7351-CAP-0402]
C230  0.01uF  [SM-7351-CAP-0402]
C231  4.7uF  [SM-7351-CAP-0603]
C232  0.1uF  [SM-7351-CAP-0402]
C233  0.1uF  [SM-7351-CAP-0402]
C234  0.1uF  [SM-7351-CAP-0402]
C235  0.1uF  [SM-7351-CAP-0402]
C236  0.1uF  [SM-7351-CAP-0402]
C237  4.7uF  [SM-7351-CAP-0603]
C238  0.1uF  [SM-7351-CAP-0402]
C239  0.1uF  [SM-7351-CAP-0402]
C240  0.1uF  [SM-7351-CAP-0402]
C241  4.7uF  [SM-7351-CAP-0603]
C242  0.1uF  [SM-7351-CAP-0402]
C243  18pF  [SM-7351-CAP-0402]
C244  18pF  [SM-7351-CAP-0402]
C245  0.1uF  [SM-7351-CAP-0402]
C420  0.01uF  [SM-7351-CAP-0402]
C425  0.01uF  [SM-7351-CAP-0402]
C426  0.01uF  [SM-7351-CAP-0402]
C443  0.01uF  [SM-7351-CAP-0402]
C444  0.01uF  [SM-7351-CAP-0402]
C448  0.01uF  [SM-7351-CAP-0402]
C577  0.01uF  [SM-7351-CAP-0402]
C578  0.01uF  [SM-7351-CAP-0402]
D13  Green LED  [sm_led_0805]
FB9  220OHM2A  [sm-7351-ind-0603]
FB10  220OHM2A  [sm-7351-ind-0603]
FB11  220OHM2A  [sm-7351-ind-0603]
FB12  150OHM800mA  [sm-7351-ind-0805]
J19  USB_MicroAB  [ZX62-AB-5PA]
R472  DNI  [SM-7351-RES-0603]
R473  0  [SM-7351-RES-0402]
R474  0  [SM-7351-RES-0402]
R475  0  [SM-7351-RES-0402]
R476  0  [SM-7351-RES-0402]
R477  0  [SM-7351-RES-0402]
R478  0  [SM-7351-RES-0402]
R479  12K, 1%  [SM-7351-RES-0402]
R480  0  [SM-7351-RES-0402]
R481  0  [SM-7351-RES-0402]
R482  0  [SM-7351-RES-0402]
R483  0  [SM-7351-RES-0402]
R484  4.7K  [SM-7351-RES-0402]
R485  10K  [SM-7351-RES-0402]
R486  0  [SM-7351-RES-0402]
R487  0  [SM-7351-RES-0402]
R489  0  [SM-7351-RES-0402]
R491  4.7K  [SM-7351-RES-0402]
R492  0  [SM-7351-RES-0402]
R493  220  [SM-7351-RES-0402]
R494  10K  [SM-7351-RES-0402]
R495  2.2K  [sm-7351-res-0402]
R496  10K  [SM-7351-RES-0402]
R554  0  [SM-7351-RES-0402]
R555  0  [SM-7351-RES-0402]
R677  0  [SM-7351-RES-0402]
TP18  TP1mm  [tp_smd1mmcircle]
U34  SN74LVC1G00DCK  [U_5_DCK]
U36  TPD2E001  [U_5_DRL]
U37  FT2232HL  [LQFP64pin]
U38  93LC56B  [SOIC_8]
U63  SN74AVC4T245  [U_16_PW]
U65  SN74AVC2T244  [son2x1-8-16m]
U75  SN74AVC2T244  [son2x1-8-16m]
U99  SN74LVC1G07  [SC70-5-43M]
U100  SN74AVC2T245  [UQFN1X2-10-22M]
U101  TLV1117-33CDCY  [SOT223-4-71M]
Y5  12MHz  [SM_OSC_ABM3]
sheet Pg24: eMMC
C255  0.01uF  [SM-7351-CAP-0402]
C256  0.01uF  [SM-7351-CAP-0402]
C257  0.01uF  [SM-7351-CAP-0402]
C258  0.01uF  [SM-7351-CAP-0402]
C261  0.01uF  [SM-7351-CAP-0402]
C262  0.01uF  [SM-7351-CAP-0402]
C263  0.01uF  [SM-7351-CAP-0402]
C264  0.01uF  [SM-7351-CAP-0402]
C265  1uF  [SM-7351-CAP-0402]
C350  1uF  [SM-7351-CAP-0402]
C479  2.2uF  [SM-7351-CAP-0805]
R505  49.9K  [SM-7351-RES-0402]
R506  49.9K  [SM-7351-RES-0402]
R507  49.9K  [SM-7351-RES-0402]
R508  49.9K  [SM-7351-RES-0402]
R509  49.9K  [SM-7351-RES-0402]
R510  49.9K  [SM-7351-RES-0402]
R511  49.9K  [SM-7351-RES-0402]
R512  49.9K  [SM-7351-RES-0402]
R513  49.9K  [SM-7351-RES-0402]
R741  10K  [SM-7351-RES-0402]
U43  MTFC16GAKAECN-2M WT  [BGA11X13-153-39M]
sheet Pg27: DCAN #1
C249  3.3uF  [SM-7351-CAP-0603]
C250  3.3uF  [SM-7351-CAP-0603]
C251  0.01uF  [SM-7351-CAP-0402]
C252  0.1uF  [SM-7351-CAP-0402]
C253  100pF25V10%  [SM-7351-CAP-0402]
C254  100pF25V10%  [SM-7351-CAP-0402]
J38  HEADER 5  [HEADER_5X1]
R502  33  [SM-7351-RES-0402]
R503  120  [SM-7351-RES-0402]
R504  33  [SM-7351-RES-0402]
U40  R1Z-3.305HP  [smd15x11-6-374m]
U41  ISO1050  [so9x6-8-191m]
U87  TPD1E10B06  [tpd1e10b06-2l]
U88  TPD1E10B06  [tpd1e10b06-2l]
sheet Pg29: RS-485
C449  0.1uF  [SM-7351-CAP-0402]
J39  HEADER 3  [header_3x1]
R582  0  [SM-7351-RES-0402]
R583  0  [SM-7351-RES-0402]
R584  0  [SM-7351-RES-0402]
R729  100, 1%  [SM-7351-RES-0402]
U77  SN65HVD78D  [soic_8]
U82  TPD1E10B06  [tpd1e10b06-2l]
U83  TPD1E10B06  [tpd1e10b06-2l]
sheet Pg31: RTC
C246  DNI  [SM-7351-CAP-0402]
C247  DNI  [SM-7351-CAP-0402]
C248  0.01uF  [SM-7351-CAP-0402]
R497  DNI  [SM-7351-RES-0402]
R498  DNI  [SM-7351-RES-0402]
R499  0  [SM-7351-RES-0402]
R500  DNI  [SM-7351-RES-0402]
R643  0  [SM-7351-RES-0402]
R645  10K  [SM-7351-RES-0402]
R919  0  [SM-7351-RES-0402]
R920  0  [SM-7351-RES-0402]
R921  0  [SM-7351-RES-0402]
R922  DNI  [SM-7351-RES-0402]
R923  DNI  [SM-7351-RES-0402]
TP19  TP1mm  [tp_smd1mmcircle]
U39  DNI SN74LVC1G07  [SC70-5-43M]
Y6  DNI_32.768KHz  [MC-306]
sheet Pg32: Expansion Connector
U1  AM5718AABCXEA  [BGA23X23-760-117M]  (sections -1,-10,-11,-12,-13,-14,-15,-16,-17,-18,-19,-2,-20,-21,-22,-23,-24,-25,-26,-27,-3,-4,-5,-6,-7,-8,-9)

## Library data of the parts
C20 C21 C85 C87 C89 C90 C93 C94 C98-C100 C245 C252 C313 C314 C579 C580 = 1C_0.1uFCapacitor16V10%0402
C22 C88 C91 C92 C95-C97 C215 C222 C317 = 1C_10uFCapacitor16V10%0805
C23 = 1C_1uFCapacitor50V10%0603
C24 C411 C412 = 1C_100uFCapacitor16V20%ElecPoly
C25 C26 = 1C_27pFCapacitor10V5%0402
C27 C449 = 1C_0.1uFCapacitor50V10%0402
C301 C302 C318 C382 C383 C392 C399 C402 C562 = 1C_2.2uFCapacitor6.3V20%X5R0402
C450 C452 = 1C_10uFCapacitor6.3V20%0603
C216 C219 C228 C230 C248 C251 C255-C258 C261-C264 C315 C408-C410 C420 C424-C429 C443 C444 C448 C451 C453 C480-C482 C577 C578 C583 = 1C_0.01uFCapacitor16V10%0402
C224 C464-C468 C479 = 1C_2.2uF16V10%SMD0805
D1 = 1E_Diode_15ARect_rev45V: TIIntPartnumber: _1E0014
D2 = 1E_Diode_SMCJ26CA: TIIntPartnumber: _1E0021
D24 D25 = TLVH431_4: DescriptiveText: Adjustable Precision Shunt Regulator; Descriptive_Text: Adjustable Precision Shunt Regulator; Mfr: TI; MfrNum: TLVH431CDBZT; PartName: Adjustable Precision Shunt Regulator
F1 = 1P_Fuse_0
J1 = 2J_Conn_PwrJack_RAPC712
J2 = 2C_Conn_LeadScrewDown_2pin
J53 = Terminal_Block_0: DescriptiveText: Conn, terminal block, 1 position; Mfr: Phoenix; MfrNum: 1792216; PartName: term_block_1pos; Vendor: Digikey
Q26 Q27 = 1Q_MOSFET_PChan_FDT434P_1: DescriptiveText: TRANS GP PNP 60V .6A; Mfr: ON Semi; MfrNum: MMBT2907AWT1G; PartName: TRANS GP PNP 60V .6A
R14 R15 R19 R20 R67 R410 R411 R416 R418 R451 R473-R478 R480-R483 R486 R487 R489 R492 R497 R499 R500 R554 R555 R558 R559 R565-R567 R572 R582-R586 R588 R634 R636 R643 R657 R658 R677 R682 R683 R792 R794-R796 R854 R906 R919-R921 = 1R_ZeroOhmResistor1_16W0402
R16 R17 = 1R_10KOhmResistor1_16W0402: DescriptiveText: Resistor 1Kohm 1/16W 5% 0402; Mfr: Panasonic; MfrNum: ERJ-2GEJ102X; PartName: 1Kohm1/16W5%SMD0402; TIIntPartnumber: 1R0027
R18 R45 R48 R412 R417 R420 R425 R428 R430-R432 R485 R494 R496 R498 R561 R570 R571 R637 R645 R741 R804 R805 R833-R835 R895 R896 R899 R900 R924 R928 R931 = 1R_10KOhmResistor1_16W0402
R21 = 1R_1KOhmResistor1_16W0402
R894 R898 = 1R_10KOhmResistor1_16W0402: DescriptiveText: Resistor 499ohm 1/16W 1% 0402; MfrNum: MCR01MZPF4990; PartName: 499ohm1/16W1%SMD0402
R897 R901 = 1R_10KOhmResistor1_16W0402: DescriptiveText: Resistor 40.2Kohm 1/16W 1% 0402; MfrNum: MCR01MZPF4022; PartName: 40.2Kohm1/16W1%SMD0402
R414 R927 = 1R_47KOhmResistor1_16W0402
SW3 = 2W_Switch_Pushbuttonsmd
TP1 TP8-TP11 = 2H_TestPointThroughHole
TP2 TP3 TP6 TP7 TP18 TP19 TP21 TP24 TP27 = 2H_Testpoint_SMD1mmCircle
U50 U83 U88 = 1A_TPD1E10B06_0
U39 U96 U99 = 1A_SN74LVC1G07
U105 = TPS3808: Supply supervisor, 5V; DescriptiveText: Supply supervisor, 5V; Descriptive_Text: Supply supervisor, 5V
Y2 = 1Y_Crystal16.384MHz
U3 = 1A_TPS659040_Indus_2
C84 C86 = 1C_0.001uFCapacitor50V5%0402
C101 = 1C_10pFCapacitor50V1%smd0402
R46 R47 = 1R_49.9OhmResistor1_16W0402
R49-R55 R57-R66 R68 R70-R75 = 1R_47ohm1_16W1%smd0402
R56 = 1R_100KOhmResistor1_16W0402
R69 R413 = 1R_10ohm1_16W5%smd0402
U8 = TPS51200
C217 C231 C237 C241 = 1C_4.7uFCapacitor16V10%0603
C218 = 1C_4.7uFCapacitor50V20%0805
C265 C350 C407 C484 = 1C_1uFCapacitor10V10%0402
FB12 FB19 = 1L_FerBead_0
J16 = 2C_Conn_FFC_0.5mm_32pos
J17 = 2C_Conn_FFC_0.5mm_6pos
J51 = 2H_Header_0
L1 = 1L_0.7Asmd
M3 = 2H_Shunt0.1in
Q9 = 1Q_MOSFET_NChan_BSS138
R415 = 1R_2OhmResistor1_10W1%0603
R630-R633 R687 = 1R_100ohm1_16W1%SMD0402
U32 = 1A_TPS61081DRC
U76 = TPS71712
U89 = 1A_TC358778XBG
U102 U103 = SN74CBTLV16292GR: FET MUX, 12-bit 1:2; DescriptiveText: FET MUX, 12-bit 1:2; Descriptive_Text: FET MUX, 12-bit 1:2; Mfr: TI; Vendor: Digikey
U104 = SN74CBTLV3257PWR: FET MUX, 4-bit 1:2; DescriptiveText: FET MUX, 4-bit 1:2; Descriptive_Text: FET MUX, 4-bit 1:2; Mfr: TI; Vendor: Digikey
J24 = 2C_Conn_HDMI_TypeA
L29-L32 = 1M_DLW21SN900HQ2L
R495 R556 R563 = 1R_2.2KOhmResistor1_16W0402
R484 R491 R560 R562 = 1R_4.7KOhmResistor1_16W0402
U46 = 1A_TPD12S016
C225 C226 C229 C232-C236 C238-C240 C242 = 1C_0.01uFCapacitor16V10%0402: Cost100: 0.11; DescriptiveText: Capacitor 0.1uF 16V 10% 0402 X7R; MfrNum: C0402C104K4RACT; PN: C0402C104K4RACT; PartName: 0.1uF16V10%SMD0402; TIIntPartnumber: 1C0089
C243 C244 = 1C_18pFCapacitor16V10%0402
D13 = 1F_LED_Green
FB9 = 1L_FerriteBead_1
FB10 = 1L_FerriteBead_1_1
FB11 = 1L_FerriteBead_1_2
J19 = 2C_MicroUSBAB: MfrNum: ZX62-AB-5PA(31)
R472 = 1R_ZeroOhmResistor1_16W0603
R479 = 1R_12Kohm1_16W1%SMD0402
R493 = 1R_220ohm1_10W1%smd0402
U34 = 1A_SN74LVC1G00DCK
U36 = 1A_TPD2E001DRL
U37 = 1A_FT2232_2
U38 = 1A_93C56EEPROM2Kbit
U63 = 1A_SN74AVC4T245
U65 U75 = 1A_SN74AVC2T244
U100 = 1A_SN74AVC2T245: DescriptiveText: Bus Transceiver 2bit Voltage Translator; MfrNum: SN74AVC2T245RSWR
U101 = TLV1117: Low Dropout 3.3V 800mA Linear Regulator; DescriptiveText: Low Dropout 3.3V 800mA Linear Regulator; Descriptive_Text: Low Dropout 3.3V 800mA Linear Regulator
Y5 = 1Y_Crystal12MHzABM3_0
R505-R513 = 1R_49.9KOhmResistor1_16W0402
U43 = 1A_EMMC16G_S100: Mfr: Micron; Vendor: Micron
C249 C250 = 1C_3.3uFCapacitor16V10%0603
C253 C254 = 1C_100pFCapacitor16V10%0402
J38 = 2H_Header_5x1
R502 R504 = 1R_33ohmResistor1_16W5%0402
R503 = 1R_120ohm1_16W1%smd0402
U40 = 1A_IsoReg5V_R1Z-3.305HP
U41 = 1A_ISO1050
U82 U87 = 1A_TPD1E10B06_0_1
J39 = 2H_Header_3x1
R729 = 1R_100ohm1_10W1%SMD0402
U77 = 1A_SN65HVD78
C246 C247 = 1C_15pFCapacitor50V10%smd0402
R922 = 1R_20.5Kohm1_16W1%smd0402
R923 = 1R_18.2Kohm1_16W1%smd0402
Y6 = 1Y_Crystal_SMD32_0
U1 = AM571X_ABCpkg_Industrial_11

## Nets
DGND: C20.2 C21.2 C22.2 C23.2 C24.2(NEG) C25.1 C26.1 C27.1 C84.2 C86.2 C88.2 C90.2 C91.2 C92.2 C93.2 C94.2 C95.2 C96.2 C97.2 C98.2 C99.2 C100.2 C101.2 C215.2 C216.2 C217.2 C218.2 C219.2 C222.2 C224.2 C225.2 C226.2 C228.1 C229.2 C230.1 C231.1 C232.2 C233.2 C234.1 C235.2 C236.2 C237.1 C238.2 C239.2 C240.1 C241.2 C242.1 C243.2 C244.2 C245.2 C246.2 C247.2 C248.2 C249.2 C251.2 C253.2 C254.2 C255.2 C256.2 C257.2 C258.2 C261.2 C262.2 C263.2 C264.2 C265.2 C301.2 C302.2 C313.2 C315.2 C317.2 C318.2 C350.2 C382.2 C383.2 C392.2 C399.2 C402.2 C407.2 C408.2 C409.2 C410.2 C411.2(NEG) C412.2(NEG) C420.2 C424.2 C425.2 C426.2 C427.2 C428.2 C429.2 C443.2 C444.2 C448.2 C449.2 C450.2 C451.2 C452.2 C453.2 C464.2 C465.2 C466.1 C467.1 C468.2 C479.2 C480.2 C481.2 C482.2 C484.2 C562.2 C577.2 C578.2 C579.2 C580.2 C583.2 D2.2(ANODE) FB12.2 J1.2 J1.3 J2.2 J16.7 J16.10 J16.13 J16.16 J16.19 J16.22 J16.MNT1 J16.MNT2 J17.6 J17.MNT1 J17.MNT2 J19.5(GND) J24.2(DAT2_S) J24.5(DAT1_S) J24.8(DAT0_S) J24.11(CLK_S) J24.17(DDC/CEC_GND) J24.MTG1 J24.MTG2 J24.MTG3 J24.MTG4 J39.3 J51.1 J53.1 J53.2 Q9.S(SOURCE) R16.2(P2) R48.1(P1) R414.1(P1) R415.1 R417.1(P1) R425.2(P2) R430.2(P2) R431.2(P2) R432.2(P2) R479.2(P2) R484.1(P1) R489.1(P1) R494.1(P1) R561.1(P1) R570.2(P2) R571.2(P2) R643.2(P2) R835.1(P1) R906.2(P2) R919.1(P1) R921.2(P2) R922.1(P1) SW3.1 SW3.2 TP8.1 TP9.1 TP10.1 TP11.1 U3.A1(PKG_GND) U3.A4(REFGND1) U3.A7(GNDANA) U3.A13(PKG_GND) U3.B2(GPADC_IN0) U3.B8(SYNCDCDC) U3.B10(PKG_GND) U3.B11(PKG_GND) U3.C1(OSC16MCAP) U3.C2(GPADC_IN1) U3.C3(GPADC_IN2) U3.D6(PKG_GND) U3.D7(PKG_GND) U3.E7(GNDANA) U3.E8(PKG_GND) U3.F5(GNDANA) U3.F6(PKG_GND) U3.F7(PKG_GND) U3.G7(PKG_GND) U3.H6(PKG_GND) U3.H7(PKG_GND) U3.J6(PKG_GND) U3.M1(PKG_GND) U3.M2(PKG_GND) U3.M12(GNDDIG) U3.M13(GNDANA) U3.N1(PKG_GND) U3.N2(VIO_GND) U3.N13(PKG_GND) U8.4(PGND) U8.8(GND) U8.11(PWRPD) U32.4(GND) U32.8(PGND) U32.PAD(TPAD) U34.3(GND) U36.4(GND) U37.1(GND.1) U37.5(GND.2) U37.10(AGND) U37.11(GND.3) U37.13(TEST) U37.15(GND.4) U37.25(GND.5) U37.35(GND.6) U37.47(GND.7) U37.51(GND.8) U38.5(VSS) U38.7(NC1) U39.3(GND) U40.1(VIN-) U41.4(GND1) U43.C4(VSSQ) U43.E7(VSS) U43.G5(VSS) U43.H10(VSS) U43.K8(VSS) U43.N2(VSSQ) U43.N5(VSSQ) U43.P4(VSSQ) U43.P6(VSSQ) U46.6(GND) U46.14(GND) U46.19(GND) U50.2 U63.2(1DIR) U63.3(2DIR) U63.8(GND) U63.9(GND) U65.5(GND) U75.5(GND) U76.2(GND) U77.5(GND) U82.2 U83.2 U89.A1(VSS) U89.A10(VSS) U89.B7(VSS) U89.D4(VSS) U89.D5(VSS) U89.D6(VSS) U89.D7(VSS) U89.E4(VSS) U89.E5(VSS) U89.E6(VSS) U89.E7(VSS) U89.E9(VSS) U89.F4(VSS) U89.F5(VSS) U89.F6(VSS) U89.F7(VSS) U89.G4(VSS) U89.G5(VSS) U89.G6(VSS) U89.G7(VSS) U89.H2(VSS) U89.H9(VSS) U89.J4(VSS) U89.J5(VSS) U89.J8(CS) U89.K10(VSS) U96.3(GND) U99.3(GND) U100.2(~{OE}) U100.3(GND) U100.10(DIR1) U101.1(GND) U102.8(GND1) U102.19(GND2) U102.38(GND3) U102.49(GND4) U103.8(GND1) U103.19(GND2) U103.38(GND3) U103.49(GND4) U104.8(GND) U104.15(~{OE}) U105.2(GND) ; also on sheet 10 11 12 14 15 16 17 18 19 20 21 22 23 24 25 26 27 28 29 30 31 32
GND_CAN1: C250.2 C252.2 J38.4 U40.4(VOUT-) U40.5(VOUT-) U41.5(GND2) U87.2 U88.2
GNDUSBJ: FB12.1 J19.S1 J19.S2 J19.S3 J19.S4
V1_2D: C480.1 C481.1 C484.1 FB19.1 U76.5(OUT) U89.A7(VDDC) U89.B1(VDDC) U89.K4(VDDC)
V1_2D_EN: R451.1(P1) U76.3(EN)
V1_8D: D24.3(Anode) D25.3(Anode) Q26.3(COLLECTOR) Q27.3(COLLECTOR) R451.2(P2) R658.1(P1) R897.1(P1) R901.1(P1) ; also on sheet 17 26 27 31
V1_8FTDI: C232.1 C235.1 C238.1 C241.1 U37.12(VCORE.1) U37.37(VCORE.2) U37.49(VREGOUT) U37.64(VCORE.3)
V1_8PHY_LDO3: C392.1 U3.K11(LDO3_OUT) ; also on sheet 31
V1_8PHY_LDO4: R854.1(P1) ; also on sheet 31
V1_8PLL: C382.1 U3.B5(LDOLN_OUT) ; also on sheet 17 31
V3_3D: C88.1 C219.1 C248.1 C249.1 C251.1 C255.1 C256.1 C257.1 C258.1 C261.1 C262.1 C263.1 C264.1 C350.1 C408.1 C409.1 C410.1 C420.1 C426.1 C428.1 C444.1 C449.1 C450.1 C451.1 C479.1 C577.1 C579.1 C580.1 J17.5 Q26.2(EMMITTER) R18.2(P2) R56.2(P2) R67.2(P2) R410.2(P2) R412.2(P2) R417.2(P2) R420.1(P1) R472.2(P2) R498.2(P2) R505.2(P2) R506.2(P2) R507.2(P2) R508.2(P2) R509.2(P2) R510.2(P2) R511.2(P2) R512.2(P2) R513.2(P2) R556.2(P2) R559.2(P2) R563.2(P2) R637.1(P1) R741.2(P2) R804.2(P2) R805.2(P2) R833.2(P2) R834.1(P1) R894.2(P2) R896.2(P2) R924.2(P2) U3.D9(VIO_IN) U8.10(VIN) U39.2(A) U39.5(VCC) U40.2(VIN+) U41.1(VCC1) U43.C6(VCCQ) U43.E6(VCC) U43.F5(VCC) U43.J10(VCC) U43.K9(VCC) U43.M4(VCCQ) U43.N4(VCCQ) U43.P3(VCCQ) U43.P5(VCCQ) U46.24(VCCA) U63.1(VCCA) U65.8(VCCB) U75.1(VCCA) U75.3(A2) U77.8(VCC) U89.B10(VDDIO) U89.H1(VDDIO) U89.K5(VDDIO) U89.K9(VDDIO) U100.1(DIR2) U100.7(VCCA) U102.17(VCC) U103.17(VCC) U104.16(VCC) ; also on sheet 10 11 12 14 15 17 18 19 20 21 22 23 24 25 26 27 28 29 30 31 32
V3_3FTDI: C224.1 C228.2 C229.1 C230.2 C233.1 C236.1 C239.1 C242.2 C245.1 C425.1 C443.1 C448.1 C578.1 FB10.2 FB11.2 R472.1(P1) R485.2(P2) R496.2(P2) U34.5(VCC) U37.20(VCCIO.1) U37.31(VCCIO.2) U37.42(VCCIO.3) U37.50(VREGIN) U37.56(VCCIO.4) U38.6(NC2) U38.8(VCC) U63.16(VCCB) U65.1(VCCA) U75.8(VCCB) U99.5(VCC) U100.6(VCCB) U101.2(VOUT1) U101.4(VOUT2)
V3_3USB: C399.1 U3.B9(LDOUSB_OUT) ; also on sheet 17
V3_7LCD: C222.1 C315.1 J16.3 J16.4 J16.5 ; also on sheet 19
V5_0D: C427.1 R560.2(P2) R562.2(P2) U46.11(VCC5V) ; also on sheet 14 15 18 19 29
V5_0HDMICONN: C429.1 J24.18(+5V) U46.13(5V_OUT)
VDD_MIPI: C424.1 C482.1 FB19.2 U89.E10(VDD_MIPI) U89.H10(VDD_MIPI)
VDD_RTC: C402.1 U3.A5(LDO9_OUT) ; also on sheet 17
VDDR_VREF: C99.1 U8.6(REFOUT) ; also on sheet 16
VDDR_VTT: C87.1 C89.1 C93.1 C94.1 C95.1 C96.1 C97.1 C98.1 C100.1 C313.1 C314.1 R49.1(P1) R50.1(P1) R51.1(P1) R52.1(P1) R53.1(P1) R54.1(P1) R55.1(P1) R57.1(P1) R58.1(P1) R59.1(P1) R60.1(P1) R61.1(P1) R62.1(P1) R63.1(P1) R64.1(P1) R65.1(P1) R66.1(P1) R68.1(P1) R69.2(P2) R70.1(P1) R71.1(P1) R72.1(P1) R73.1(P1) R74.1(P1) R75.1(P1) U8.3(VO)
VDDS_DDR: C84.1 C85.2 C87.2 C89.2 C90.1 C91.1 C92.1 C314.2 R45.2(P2) U8.2(VLDOIN) ; also on sheet 16 17 19
6PORT_LCDn: J51.2 R924.1(P1) U102.1(S) U103.1(S) U104.1(S) ; also on sheet 29
AM57XX_GPIO_RS485: R584.2(P2) U1.AA3(MCASP5_ACLKX/PR2_PRU1_R30_1)
AM57XX_HDMI_CLK+: L29.4 U1.AH16(HDMI1_CLOCKY)
AM57XX_HDMI_CLK-: L29.1 U1.AG16(HDMI1_CLOCKX)
AM57XX_HDMI_TX0+: L30.4 U1.AH17(HDMI1_DATA0Y)
AM57XX_HDMI_TX0-: L30.1 U1.AG17(HDMI1_DATA0X)
AM57XX_HDMI_TX1+: L31.4 U1.AH18(HDMI1_DATA1Y)
AM57XX_HDMI_TX1-: L31.1 U1.AG18(HDMI1_DATA1X)
AM57XX_HDMI_TX2+: L32.4 U1.AH19(HDMI1_DATA2Y)
AM57XX_HDMI_TX2-: L32.1 U1.AG19(HDMI1_DATA2X)
AM57XX_UART2_RXD: R583.2(P2) U1.D28(UART2_RXD)
AM57XX_UART2_TXD: R582.2(P2) U1.D26(UART2_TXD)
AM57XX_UART3_RXD: R487.1(P1) ; also on sheet 29
AM57XX_UART3_TXD: R486.1(P1) ; also on sheet 29
AM57XX_VOUT1_D0: U1.F11(VOUT1_D0) U103.4(A2)
AM57XX_VOUT1_D1: U1.G10(VOUT1_D1) U103.2(A1)
AM57XX_VOUT1_D2: U1.F10(VOUT1_D2) U103.11(A5)
AM57XX_VOUT1_D3: U1.G11(VOUT1_D3) U103.13(A6)
AM57XX_VOUT1_D4: U1.E9(VOUT1_D4) U103.25(A11)
AM57XX_VOUT1_D5: U1.F9(VOUT1_D5) U103.9(A4)
AM57XX_VOUT1_D6: U1.F8(VOUT1_D6) U103.6(A3)
AM57XX_VOUT1_D7: U1.E7(VOUT1_D7) U103.15(A7)
AM57XX_VOUT1_D8: U1.E8(VOUT1_D8) U103.21(A9)
AM57XX_VOUT1_D9: U1.D9(VOUT1) U103.27(A12)
AM57XX_VOUT1_D10: U1.D7(VOUT1_D10) U103.18(A8)
AM57XX_VOUT1_D11: U1.D8(VOUT1_D11) U103.23(A10)
AM57XX_VOUT1_D12: U1.A5(VOUT1_D12) U102.9(A4)
AM57XX_VOUT1_D13: U1.C6(VOUT1_D13) U102.2(A1)
AM57XX_VOUT1_D14: U1.C8(VOUT1_D14) U102.6(A3)
AM57XX_VOUT1_D15: U1.C7(VOUT1_D15) U102.4(A2)
AM57XX_VOUT1_D16: U1.B7(VOUT1_D16) U102.13(A6)
AM57XX_VOUT1_D17: U1.B8(VOUT1_D17) U102.18(A8)
AM57XX_VOUT1_D18: U1.A7(VOUT1_D18) U102.15(A7)
AM57XX_VOUT1_D19: U1.A8(VOUT1_D19) U102.21(A9)
AM57XX_VOUT1_D20: U1.C9(VOUT1_D20) U102.11(A5)
AM57XX_VOUT1_D21: U1.A9(VOUT1_D21) U102.25(A11)
AM57XX_VOUT1_D22: U1.B9(VOUT1_D22) U102.23(A10)
AM57XX_VOUT1_D23: U1.A10(VOUT1_D23) U102.27(A12)
AM57XX_VOUT1_DE: R634.2(P2) U1.B10(VOUT1_DE)
AM57XX_VOUT1_HSYNC: R636.2(P2) U1.C11(VOUT1_HSYNC)
AM57XX_VOUT1_PCLK: R565.2(P2) U1.D11(VOUT1_CLK)
AM57XX_VOUT1_VSYNC: U1.E11(VOUT1_VSYNC) U104.4(A1)
AM571X_VIN2A_D2: R416.2(P2) U1.D1(VIN2A_D2/eCAP1_IN_PWM1) ; also on sheet 29
AM572X_DCAN1_RX: C253.1 R502.1 U1.G19(DCAN1_RX)
AM572X_DCAN1_TX: R504.1 U1.G20(DCAN1_TX)
AM572X_HDMI_CEC: R683.2(P2) R805.1(P1) U1.B20(SPI1_CS3/HDMI_CEC)
AM572X_HDMI_DDC_SCL: R556.1(P1) R795.2(P2) U1.C25(I2C2_SDA/HDMI1_DDC_SCL) ; also on sheet 26
AM572X_HDMI_DDC_SDA: R563.1(P1) R796.2(P2) U1.F17(I2C2_SCL/HDMI1_DDC_SDA) ; also on sheet 26
AM572X_HDMI_HPD: R682.2(P2) R804.1(P1) U1.B21(SPI1_CS2/HDMI_HPD)
BKLT_EN: Q9.G(GATE) R412.1(P1) R416.1(P1)
BKLT_L: L1.1 U32.1(L)
BKLT_SW: L1.2 U32.10(SW)
CAN1_H: J38.2 R503.2(P2) U41.7(CANH) U88.1
CAN1_L: J38.3 R503.1(P1) U41.6(CANL) U87.1
CAN1_RXDF: R502.2 U41.2(RXD) ; also on sheet 29
CAN1_TXDF: C254.1 R504.2 U41.3(TXD) ; also on sheet 29
DDR_A0: R54.2(P2) ; also on sheet 16
DDR_A1: R57.2(P2) ; also on sheet 16
DDR_A2: R55.2(P2) ; also on sheet 16
DDR_A3: R58.2(P2) ; also on sheet 16
DDR_A4: R59.2(P2) ; also on sheet 16
DDR_A5: R60.2(P2) ; also on sheet 16
DDR_A6: R61.2(P2) ; also on sheet 16
DDR_A7: R62.2(P2) ; also on sheet 16
DDR_A8: R63.2(P2) ; also on sheet 16
DDR_A9: R64.2(P2) ; also on sheet 16
DDR_A10: R66.2(P2) ; also on sheet 16
DDR_A11: R65.2(P2) ; also on sheet 16
DDR_A12: R68.2(P2) ; also on sheet 16
DDR_A13: R70.2(P2) ; also on sheet 16
DDR_A14: R71.2(P2) ; also on sheet 16
DDR_BA0: R72.2(P2) ; also on sheet 16
DDR_BA1: R73.2(P2) ; also on sheet 16
DDR_BA2: R74.2(P2) ; also on sheet 16
DDR_CASn: R52.2(P2) ; also on sheet 16
DDR_CKE: R49.2(P2) ; also on sheet 16
DDR_CLK: R46.2(P2) ; also on sheet 16
DDR_CLKn: R47.2(P2) ; also on sheet 16
DDR_CS0n: R50.2(P2) ; also on sheet 16
DDR_ODT: R75.2(P2) ; also on sheet 16
DDR_RASn: R51.2(P2) ; also on sheet 16
DDR_WEn: R53.2(P2) ; also on sheet 16
EECS: U37.63(EECS) U38.1(CS)
EEDATA: R495.1(P1) U37.61(EEDATA) U38.3(DI)
EESK: U37.62(EESK) U38.2(CLK)
eMMC_RSTn: R741.1(P1) U43.K5(RSTn) ; also on sheet 29
EMU_USB_DM: J19.2(DM) U36.5(IO2) U37.7(DM)
EMU_USB_DP: J19.3(DP) U36.3(IO1) U37.8(DP)
F_ADBUS0: R474.2(P2) U37.16(ADBUS0)
F_ADBUS1: R475.2(P2) U37.17(ADBUS1)
F_ADBUS2: R480.2(P2) U37.18(ADBUS2)
F_ADBUS3: R481.2(P2) U37.19(ADBUS3)
F_ADBUS4: R476.2(P2) U37.21(ADBUS4)
F_ADBUS5: R478.2(P2) U37.26(ACBUS0)
F_ADBUS6: R477.2(P2) U37.23(ADBUS6)
F_ADBUS7: R483.2(P2) U37.30(ACBUS4)
FT_SRESET: R478.1(P1) R484.2(P2) U34.1(A)
FT_SRESETB: R473.2(P2) U99.4(Y)
FT_SRESETn: U34.4(Y) U99.2(A)
FT_VBUS: R492.1(P1) U34.2(B)
FTDI_REF: R479.1(P1) U37.6(REF)
FTDI_VPHY: C231.2 C234.2 FB10.1 U37.4(VPHY)
FTDI_VPLL: C237.2 C240.2 FB11.1 U37.9(VPLL)
GPIO_TOUCH_RESETn: R792.2(P2) ; also on sheet 29
GPIO_USB2_VBUS_DET: R834.2(P2) U96.4(Y) ; also on sheet 29
HDMI_CEC: R683.1(P1) U46.1(CEC_A)
HDMI_CLK+: J24.10(CLK+) L29.3 U46.16(TMDS_CK+)
HDMI_CLK-: J24.12(CLK-) L29.2 U46.15(TMDS_CK-)
HDMI_CT_HPD: R558.2(P2) R559.1(P1) U46.12(CT_HPD)
HDMI_DDC_SCL: R795.1(P1) U46.2(SCL_A)
HDMI_DDC_SDA: R796.1(P1) U46.3(SDA_A)
HDMI_HPLG: R682.1(P1) U46.4(HPD_A)
HDMI_LSOE: R558.1(P1) U46.5(LS_OE)
HDMI_TX0+: J24.7(DAT0+) L30.3 U46.18(TMDS_D0+)
HDMI_TX0-: J24.9(DAT0-) L30.2 U46.17(TMDS_D0-)
HDMI_TX1+: J24.4(DAT1+) L31.3 U46.21(TMDS_D1+)
HDMI_TX1-: J24.6(DAT1-) L31.2 U46.20(TMDS_D1-)
HDMI_TX2+: J24.1(DAT2+) L32.3 U46.23(TMDS_D2+)
HDMI_TX2-: J24.3(DAT2-) L32.2 U46.22(TMDS_D2-)
HDMICONN_CEC: J24.13(CEC) U46.7(CEC_B)
HDMICONN_HPLG: J24.19(HPLG) R561.2(P2) U46.10(HPD_B)
HDMICONN_I2CSCL: J24.15(SCL) R560.1(P1) U46.8(SCL_B)
HDMICONN_I2CSDA: J24.16(SDA) R562.1(P1) U46.9(SDA_B)
IND_I2C_SCL: J17.2 R14.2(P2) R567.2(P2) ; also on sheet 10 11 18 20 27 29
IND_I2C_SDA: J17.1 R15.2(P2) R585.2(P2) ; also on sheet 10 11 18 20 27 29
JTAG_EMU0: R554.1(P1) ; also on sheet 10
JTAG_EMU1: R555.1(P1) ; also on sheet 10
JTAG_TCK: U63.4(1A1) ; also on sheet 10
JTAG_TDI: U63.5(1A2) ; also on sheet 10
JTAG_TDO: U75.2(A1) ; also on sheet 10
JTAG_TMS: U63.6(2A1) ; also on sheet 10
JTAG_TRSTn: U63.7(2A2) ; also on sheet 10
JTAGPOD_PRES: R677.1(P1) ; also on sheet 10
LCD_B0: U89.J3(PD0) U103.52(1B2)
LCD_B1: U89.K3(PD1) U103.54(1B1)
LCD_B2: U89.J2(PD2) U103.45(1B5)
LCD_B3: U89.K2(PD3) U103.43(1B6)
LCD_B4: U89.J1(PD4) U103.32(1B11)
LCD_B5: U89.K1(PD5) U103.47(1B4)
LCD_B6: U89.G2(PD6) U103.50(1B3)
LCD_B7: U89.G1(PD7) U103.41(1B7)
LCD_CLKN: J16.20 R632.1(P1) U89.F10(MIPI_CN)
LCD_CLKP: J16.21 R632.2(P2) U89.F9(MIPI_CP)
LCD_DEN: R634.1(P1) U89.J7(DE)
LCD_G0: U89.F2(PD8) U103.36(1B9)
LCD_G1: U89.F1(PD9) U103.30(1B12)
LCD_G2: U89.E2(PD10) U103.39(1B8)
LCD_G3: U89.E1(PD11) U103.34(1B10)
LCD_G4: U89.D2(PD12) U102.47(1B4)
LCD_G5: U89.D1(PD13) U102.54(1B1)
LCD_G6: U89.C2(PD14) U102.50(1B3)
LCD_G7: U89.C1(PD15) U102.52(1B2)
LCD_HS: R636.1(P1) U89.K8(HSYNC)
LCD_MIPI0N: J16.17 R630.2(P2) U89.J10(MIPI_D0N)
LCD_MIPI0P: J16.18 R630.1(P1) U89.J9(MIPI_D0P)
LCD_MIPI1N: J16.14 R631.2(P2) U89.G10(MIPI_D1N)
LCD_MIPI1P: J16.15 R631.1(P1) U89.G9(MIPI_D1P)
LCD_MIPI2N: J16.11 R633.1(P1) U89.D10(MIPI_D2N)
LCD_MIPI2P: J16.12 R633.2(P2) U89.D9(MIPI_D2P)
LCD_MIPI3N: J16.8 R687.1(P1) U89.C10(MIPI_D3N)
LCD_MIPI3P: J16.9 R687.2(P2) U89.C9(MIPI_D3P)
LCD_PCLK: R565.1(P1) U89.J6(PCLK)
LCD_R0: U89.B2(PD16) U102.43(1B6)
LCD_R1: U89.A2(PD17) U102.39(1B8)
LCD_R2: U89.B3(PD18) U102.41(1B7)
LCD_R3: U89.A3(PD19) U102.36(1B9)
LCD_R4: U89.B4(PD20) U102.45(1B5)
LCD_R5: U89.A4(PD21) U102.32(1B11)
LCD_R6: U89.B5(PD22) U102.34(1B10)
LCD_R7: U89.A5(PD23) U102.30(1B12)
LCD_VS: U89.K7(VSYNC) U104.2(1B1)
MMC2_CLK: U1.J7(GPMC_A23/MMC2_CLK) U43.M6(CLK)
MMC2_CMD: R513.1(P1) U1.H6(GPMC_CS1/MMC2_CMD) U43.M5(CMD)
MMC2_DAT0: R505.1(P1) U1.J4(GPMC_A24/MMC2_DAT0) U43.A3(DAT0)
MMC2_DAT1: R506.1(P1) U1.J6(GPMC_A25/MMC2_DAT1) U43.A4(DAT1)
MMC2_DAT2: R507.1(P1) U1.H4(GPMC_A26/MMC2_DAT2) U43.A5(DAT2)
MMC2_DAT3: R508.1(P1) U1.H5(GPMC_A27/MMC2_DAT3) U43.B2(DAT3)
MMC2_DAT4: R509.1(P1) U1.K7(GPMC_A19/MMC2_DAT4) U43.B3(DAT4)
MMC2_DAT5: R510.1(P1) U1.M7(GPMC_A20/MMC2_DAT5) U43.B4(DAT5)
MMC2_DAT6: R511.1(P1) U1.J5(GPMC_A21/MMC2_DAT6) U43.B5(DAT6)
MMC2_DAT7: R512.1(P1) U1.K6(GPMC_A22/MMC2_DAT7) U43.B6(DAT7)
PMIC_EN: R645.1(P1) R922.2(P2) R923.1(P1) U3.E5(nSLEEP)
PMIC_INT: U3.K1(INT) ; also on sheet 29
PMIC_RESET_IN: R794.2(P2) R928.2(P2) U105.1(~{RESET})
PMIC_RESET_OUTn: R833.1(P1) U3.G6(RESET_OUT) ; also on sheet 30
PORZn: R499.1(P1) R920.1(P1) ; also on sheet 30
PR1_MII0_COL: U102.33(2B10) ; also on sheet 23 29
PR1_MII0_CRS: U102.29(2B12) ; also on sheet 23
PR1_MII0_RXD0: U102.35(2B9) ; also on sheet 23 29
PR1_MII0_RXD1: U102.40(2B7) ; also on sheet 23 29
PR1_MII0_RXD2: U102.37(2B8) ; also on sheet 23 29
PR1_MII0_RXD3: U102.42(2B6) ; also on sheet 23 29
PR1_MII0_RXDV: U102.51(2B2) ; also on sheet 23 29
PR1_MII0_RXER: U102.44(2B5) ; also on sheet 23 29
PR1_MII0_RXLINK: U102.31(2B11) ; also on sheet 23 29
PR1_MII0_TXD0: U102.53(2B1) ; also on sheet 23 29
PR1_MII0_TXD1: U102.46(2B4) ; also on sheet 23 29
PR1_MII0_TXD2: U103.37(2B8) ; also on sheet 23 29
PR1_MII0_TXD3: U103.29(2B12) ; also on sheet 23 29
PR1_MII0_TXEN: U103.33(2B10) ; also on sheet 23 29
PR1_MII1_CRS: U103.53(2B1) ; also on sheet 22 29
PR1_MII1_MR1_CLK: U103.44(2B5) ; also on sheet 22 29
PR1_MII1_RXD0: U103.40(2B7) ; also on sheet 22 29
PR1_MII1_RXD1: U103.48(2B3) ; also on sheet 22 29
PR1_MII1_RXD2: U103.46(2B4) ; also on sheet 22 29
PR1_MII1_RXD3: U103.31(2B11) ; also on sheet 22 29
PR1_MII1_RXDV: U103.42(2B6) ; also on sheet 22 29
PR1_MII1_RXER: U104.3(2B1) ; also on sheet 22
PR1_MII1_RXLINK: U103.51(2B2) ; also on sheet 22
PR1_MII_MR0_CLK: U102.48(2B3) ; also on sheet 23 29
PR1_MII_MT0_CLK: U103.35(2B9) ; also on sheet 23 29
RS485_A: J39.1 R729.2(P2) U77.6(A) U82.1
RS485_B: J39.2 R729.1(P1) U77.7(B) U83.1
RSTOUTTOPMIC: U3.E6(nRESWARM) ; also on sheet 30
SRCCLK: R586.2(P2) ; also on sheet 11
SYS_RESETn: R566.2(P2) ; also on sheet 28 29 30
SYS_WARMRESETn: R473.1(P1) ; also on sheet 10 30
TOUCH_INT: R418.2(P2) ; also on sheet 29
TSC_INT: J17.4 R418.1(P1)
TSC_RESETn: J17.3 R420.2(P2) R792.1(P1)
UARTx_RXD: U37.38(BDBUS0) U100.5(B1)
UARTx_TXD: U37.39(BDBUS1) U100.4(B2)
USBJTAG_ENn: R677.2(P2) U63.14(2~{OE}) U63.15(1~{OE}) U65.4(~{OE}) U75.4(~{OE})
VANA_OUT: C302.1 U3.C8(LDOVANA_OUT)
VCAN1: C250.1 C252.1 J38.1 U40.7(VOUT+) U41.8(VCC2)
VLDO1_OUT: C383.1 R657.2(P2) U3.C6(LDO1_OUT)
VLDO2_OUT: C318.1 R658.2(P2) U3.B6(LDO2_OUT)
VLED+: C215.1 C216.1 C218.1 J16.29 J16.30 U32.9(OUT)
VLED-: J16.23 J16.24 J16.25 J16.26 J16.27 J16.28 R415.2 U32.5(FB)
VMAIN: C20.1 C21.1 C22.1 C23.1 C24.1(POS) C217.1 C317.1 C407.1 C411.1(POS) C412.1(POS) C452.1 C453.1 C464.1 C465.1 C466.2 C467.2 C468.1 D2.1(CATHODE) F1.2 R19.2(P2) R20.2(P2) R411.2(P2) R927.2(P2) TP1.1 U3.A6(LDO12_IN) U3.A9(LDOUSB_IN2) U3.A10(LDO7_LDOUSB_IN) U3.C4(LDO9_IN) U3.C5(LDOLN_IN) U3.C7(VCC1) U3.L12(LDO34_IN) U3.L13(LDO34_IN1) U3.M4(LDO58_IN) U3.N3(LDO6_IN) U3.N4(LDO58_IN) U32.2(VIN) U76.1(IN) U96.5(VCC) U105.6(VDD) ; also on sheet 11 19 29
VPWRIN_JCK: D1.2(ANODE) J1.1 J2.1 U105.5(SENSE)
VPWRIN_PREFUSE: D1.1(CATHODE) F1.1
VRTC_OUT: C301.1 R17.2(P2) R645.2(P2) R928.1(P1) R931.2(P2) U3.A8(LDOVRTC_OUT) ; also on sheet 17
VSDMMC: Q27.2(EMMITTER) R657.1(P1) R898.2(P2) R900.2(P2) ; also on sheet 17 25 31
VUSB_FTDI: C226.1 D13.2(Anode) FB9.2 R491.2(P2) U101.3(VIN)
VUSB_JTAG: C225.1 FB9.1 J19.1(VBUS) U36.1(VCC)
VUSB_VBUS2: R21.2(P2) ; also on sheet 14
XTIN: C243.1 U37.2(XTIN) Y5.1
XTOUT: C244.1 U37.3(XTOUT) Y5.2
N11217419: C85.1 R46.1(P1) R47.1(P1)
N11219802: R67.1(P1) U8.7(EN)
N11219922: R56.1(P1) U8.9(PGOOD)
N11219986: C101.1 R69.1(P1) U8.5(VOSNS)
N11220684: C86.1 R45.1(P1) R48.2(P2) U8.1(REFIN)
N12957779: R482.2(P2) U37.28(ACBUS2)
N12957783: R482.1(P1) U75.6(B2)
N12957791: R489.2(P2) U37.32(ACBUS5)
N12957851: R491.1(P1) R492.2(P2) R494.2(P2) U37.59(BCBUS7)
N12958009: R485.1(P1) U37.14(RESET#)
N12958129: D13.1(Cathode) R493.2
N12958219: R495.2(P2) R496.1(P1) U38.4(DO)
N12958339: TP18.1 U37.36(SUSPEND#)
N12958347: R493.1 U37.60(PWREN#)
N12958879: R474.1(P1) U63.13(1B1)
N12958935: R476.1(P1) U63.10(2B2)
N12958939: R481.1(P1) U63.11(2B1)
N12958943: R480.1(P1) U75.7(B1)
N12958955: R475.1(P1) U63.12(1B2)
N17732522: R410.1(P1) U32.6(EN)
N17732526: R413.2(P2) R414.2(P2) U32.3(SS)
N17732536: Q9.D(DRAIN) R413.1(P1)
N17732560: R411.1(P1) U32.7(FSW)
N18733248: R497.1(P1) U1.AD14(RTC_OSC_XO)
N18733249: C247.1 R497.2(P2) Y6.4
N18733252: C246.1 R919.2(P2) U1.AE14(RTC_OSC_XI) Y6.1
N18733262: R499.2(P2) U1.AF14(RTC_ISO)
N18733263: R498.1(P1) R500.1(P1) U39.4(Y)
N18733273: R500.2(P2) R920.2(P2) U1.AB17(RTC_PORZ)
N18733274: R923.2(P2) U1.Y11(ON_OFF)
N18733276: R921.1(P1) TP19.1 U1.AD17(WAKEUP0)
N18868530: R14.1(P1) R572.2(P2) U3.L1(I2C1_SCL_SCK)
N18868533: R15.1(P1) R588.2(P2) U3.L2(I2C1_SDA_SDI)
N18901325: R794.1(P1) U3.K9(RESET_IN)
N18913166: TP7.1 U3.J5(ENABLE1)
N18913202: R17.1(P1) R906.1(P1) U3.K7(BOOT1)
N18913205: R16.1(P1) U3.L3(BOOT0)
N18913322: R18.1(P1) R931.1(P1) U3.G9(GPIO_7)
N18913403: C26.2 U3.A3(OSC16MIN) Y2.1
N18913412: C25.2 U3.A2(OSC16MOUT) Y2.3
N18913758: C27.2 U3.B7(VBG)
N18914190: TP2.1 U3.M11(CLK32KGO)
N18914214: TP3.1 U3.J7(POWERGOOD)
N18914339: SW3.3 SW3.4 U3.G8(PWRON) U50.1
N18914524: TP6.1 U3.C11(RPWRON)
N18915671: R19.1(P1) U3.B3(VCC_SENSE)
N18915723: R20.1(P1) U3.A11(VCC_SENSE2)
N18915943: R21.1(P1) U3.D8(VBUS)
N19388440: R566.1(P1) U89.B9(RESXn)
N19438966: R582.1(P1) U1.AB9(MCASP5_FSX/PR2_PRU1_R31_2) U77.4(D)
N19438972: R583.1(P1) U77.1(R)
N19438984: R584.1(P1) U77.2(~{RE}) U77.3(DE)
N19795587: R425.1(P1) U3.B12(GPIO_0)
N19795594: R428.1(P1) U3.C13(GPIO_1)
N19795604: R430.1(P1) U3.A12(GPIO_2)
N19795606: R431.1(P1) U3.H9(GPIO_3)
N19795618: R570.1(P1) U3.C10(GPIO_5)
N19795620: R571.1(P1) U3.N11(GPIO_6)
N19795629: R432.1(P1) U3.K10(GPIO_4)
N19796448: R572.1(P1) U3.M3(I2C2_SCL_SCE)
N19796451: R588.1(P1) U3.H8(I2C2_SDA_SDO)
N20144297: R637.2(P2) U89.A9(MSEL)
N20202943: TP21.1 U3.F8(REGEN1)
N20204529: R643.1(P1) U1.AC16(WAKEUP3)
N20706534: R554.2(P2) U65.7(B1)
N20706536: R555.2(P2) U65.6(B2)
N20706626: R477.1(P1) U65.2(A1)
N20706635: R483.1(P1) U65.3(A2)
N21099488: C265.1 U43.C2(VDDI)
N21306186: TP24.1 U89.B6(GPIO1)
N21306311: R567.1(P1) U89.A8(I2C_SCL)
N21306314: R585.1(P1) U89.B8(I2C_SDA)
N21307911: R586.1(P1) U89.K6(REFCLK)
N22688543: R428.2(P2) R835.2(P2) U96.2(A)
N22829911: C562.1 R854.2(P2) U3.K12(LDO4_OUT)
N23040939: D24.2(Cathode) Q26.1(BASE) R894.1(P1) R895.1(P1)
N23040957: D24.1(REF) R895.2(P2) R896.1(P1) R897.2(P2)
N23041291: D25.2(Cathode) Q27.1(BASE) R898.1(P1) R899.1(P1)
N23041299: D25.1(REF) R899.2(P2) R900.1(P1) R901.2(P2)
N23423235: R487.2(P2) U100.8(A1)
N23423238: R486.2(P2) U100.9(A2)
N23520464: C583.1 R927.1(P1) U105.4(CT)
N23520486: TP27.1 U105.3(~{MR})

Not connected (* = marked no-connect by the designer): J16 1* 2* 6* 31* 32*; J19 4(ID)*; J24 14(NC)*; J38 5*; U3 B4(GPADC_REF) C9(LDO7_OUT) K4(LDO5_OUT) K5(LDO8_OUT) K8(PWRDOWN) L4(LDO6_OUT) N12(VPROG/TESTV); U36 2(NC)*; U37 22(ADBUS5)* 24(ADBUS7)* 27(ACBUS1)* 29(ACBUS3)* 33(ACBUS6)* 34(ACBUS7)* 40(BDBUS2)* 41(BDBUS3)* 43(BDBUS4)* 44(BDBUS5)* 45(BDBUS6)* 46(BDBUS7)* 48(BCBUS0)* 52(BCBUS1)* 53(BCBUS2)* 54(BCBUS3)* 55(BCBUS4)* 57(BCBUS5)* 58(BCBUS6)*; U39 1(NC)*; U40 10(NC)*; U43 A1(NCA1)* A2(NCA2)* A6(RFUA6) A7(RFUA7) A8(NCA8)* A9(NCA9)* A10(NCA10)* A11(NCA11)* A12(NCA12)* A13(NCA13)* A14(NCA14)* B1(NCB1) B7(NCB7) B8(NCB8) B9(NCB9) B10(NCB10) B11(NCB11) B12(NCB12) B13(NCB13) B14(NCB14) C1(NCC1) C3(NCC3) C5(NCC5) C7(NCC7) C8(NCC8) C9(NCC9) C10(NCC10) C11(NCC11) C12(NCC12) C13(NCC13) C14(NCC14) D1(NCD1) D2(NCD2) D3(NCD3) D4(NCD4) D12(NCD12) D13(NCD13) D14(NCD14) E1(NCE1) E2(NCE2) E3(NCE3) E5(RFUE5) E8(RFUE8) E9(RFUE9) E10(RFUE10) E12(NCE12) E13(NCE13) E14(NCE14) F1(NCF1) F2(NCF2) F3(NCF3) F10(RFUF10) F12(NCF12) F13(NCF13) F14(NCF14) G1(NCG1) G2(NCG2) G3(RFUG3) G10(RFUG10) G12(NCG12) G13(NCG13) G14(NCG14) H1(NCH1) H2(NCH2) H3(NCH3) H5(RFUH5) H12(NCH12) H13(NCH13) H14(NCH14) J1(NCJ1) J2(NCJ2) J3(NCJ3) J5(RFUJ5) J12(NCJ12) J13(NCJ13) J14(NCJ14) K1(NCK1) K2(NCK2) K3(NCK3) K6(RFUK6) K7(RFUK7) K10(RFUK10) K12(NCK12) K13(NCK13) K14(NCK14) L1(NCL1) L2(NCL2) L3(NCL3) L12(NCL12) L13(NCL13) L14(NCL14) M1(NCM1) M2(NCM2) M3(NCM3) M7(NCM7) M8(NCM8) M9(NCM9) M10(NCM10) M11(NCM11) M12(NCM12) M13(NCM13) M14(NCM14) N1(NCN1) N3(NCN3) N6(NCN6) N7(NCN7) N8(NCN8) N9(NCN9) N10(NCN10) N11(NCN11) N12(NCN12) N13(NCN13) N14(NCN14) P1(NCP1) P2(NCP2) P7(RFUP7) P8(NCP8) P9(NCP9) P10(RFUP10) P11(NCP11) P12(NCP12) P13(NCP13) P14(NCP14); U76 4(NR)*; U89 A6(GPIO2)*; U96 1(NC)*; U99 1(NC)*; U102 3(NC1)* 5(NC2)* 7(NC3)* 10(NC4)* 12(NC5)* 14(NC6)* 16(NC7)* 20(NC8)* 22(NC9)* 24(NC10)* 26(NC11)* 28(NC12)* 55(NC14)* 56(NC13)*; U103 3(NC1)* 5(NC2)* 7(NC3)* 10(NC4)* 12(NC5)* 14(NC6)* 16(NC7)* 20(NC8)* 22(NC9)* 24(NC10)* 26(NC11)* 28(NC12)* 55(NC14)* 56(NC13)*; U104 5(1B2)* 6(2B2)* 7(A2)* 9(A3)* 10(2B3)* 11(1B3)* 12(A4)* 13(2B4)* 14(1B4)*; Y2 2(NC0)* 4(NC1)*; Y6 2 3

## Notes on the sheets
sheet 1
- USB JTAG
- RESET# should have 0.01uF
  capacitor to ground
sheet 2
- eMMC Memory
sheet 4
- LCD Module
- PR2_EDC_LATCH1
- PR2_EDC_LATCH0
- PR2_EDC_SYNC0
- PR2_EDC_SYNC1
- BackLight Power
- PR2_UART0_RXD
- PR2_UART0_TXD
sheet 5
- CT_HPD can be connected to a GPIO to allow the
  entire TPD12S016 to be powered down.  Please
  see recommendations in the TPD12S016 datasheet.
- LS_OE can be connected to the HPD_A pin such
  that the level translators are enabled after
  hot plug is detected.  Please see
  recommendations in the TPD12S016 datasheet.
sheet 9
- Main 5VDC Power Input
- Sufficient capacitance needed to
  hold up VMAIN (over 2.7V) for at
  least 1ms after power supply
  shut off.  AM57xx device will be
  in POR reset.  This will allow
  the PMIC to properly execute its
  power-down sequence.
- Clamp circuits added to guarantee the 3.3V
  supplies V3_3D and VSDMMC never become
  more than 2V above V1_8D during start-up
  or shut-down.
- It has been later determined that the clamp
  circuit on VSDMMC is not sufficient and the
  PMIC was enhanced to better control
  shut-down sequencing.  Therefore, the
  VDSMMC clamp is no longer required. The
  power-down sequence defined in the Data
  Manual must be met.
- Whenever you copy this schematic page into your
  design, you must not ground OSC16MCAP as shown
  here.  The IDK board design has this connected
  incorrectly.  It must be connected to a 2.2uF
  capacitor as stated in the TPS659037x
  documentation.
- Always On, Pushbutton Start
- Always On, Automatic Start
- Attach to Earth Ground, if desired
